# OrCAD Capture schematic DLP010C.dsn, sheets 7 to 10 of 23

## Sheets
7 PAGE 06 - VIRTEX5 - 3: size Custom
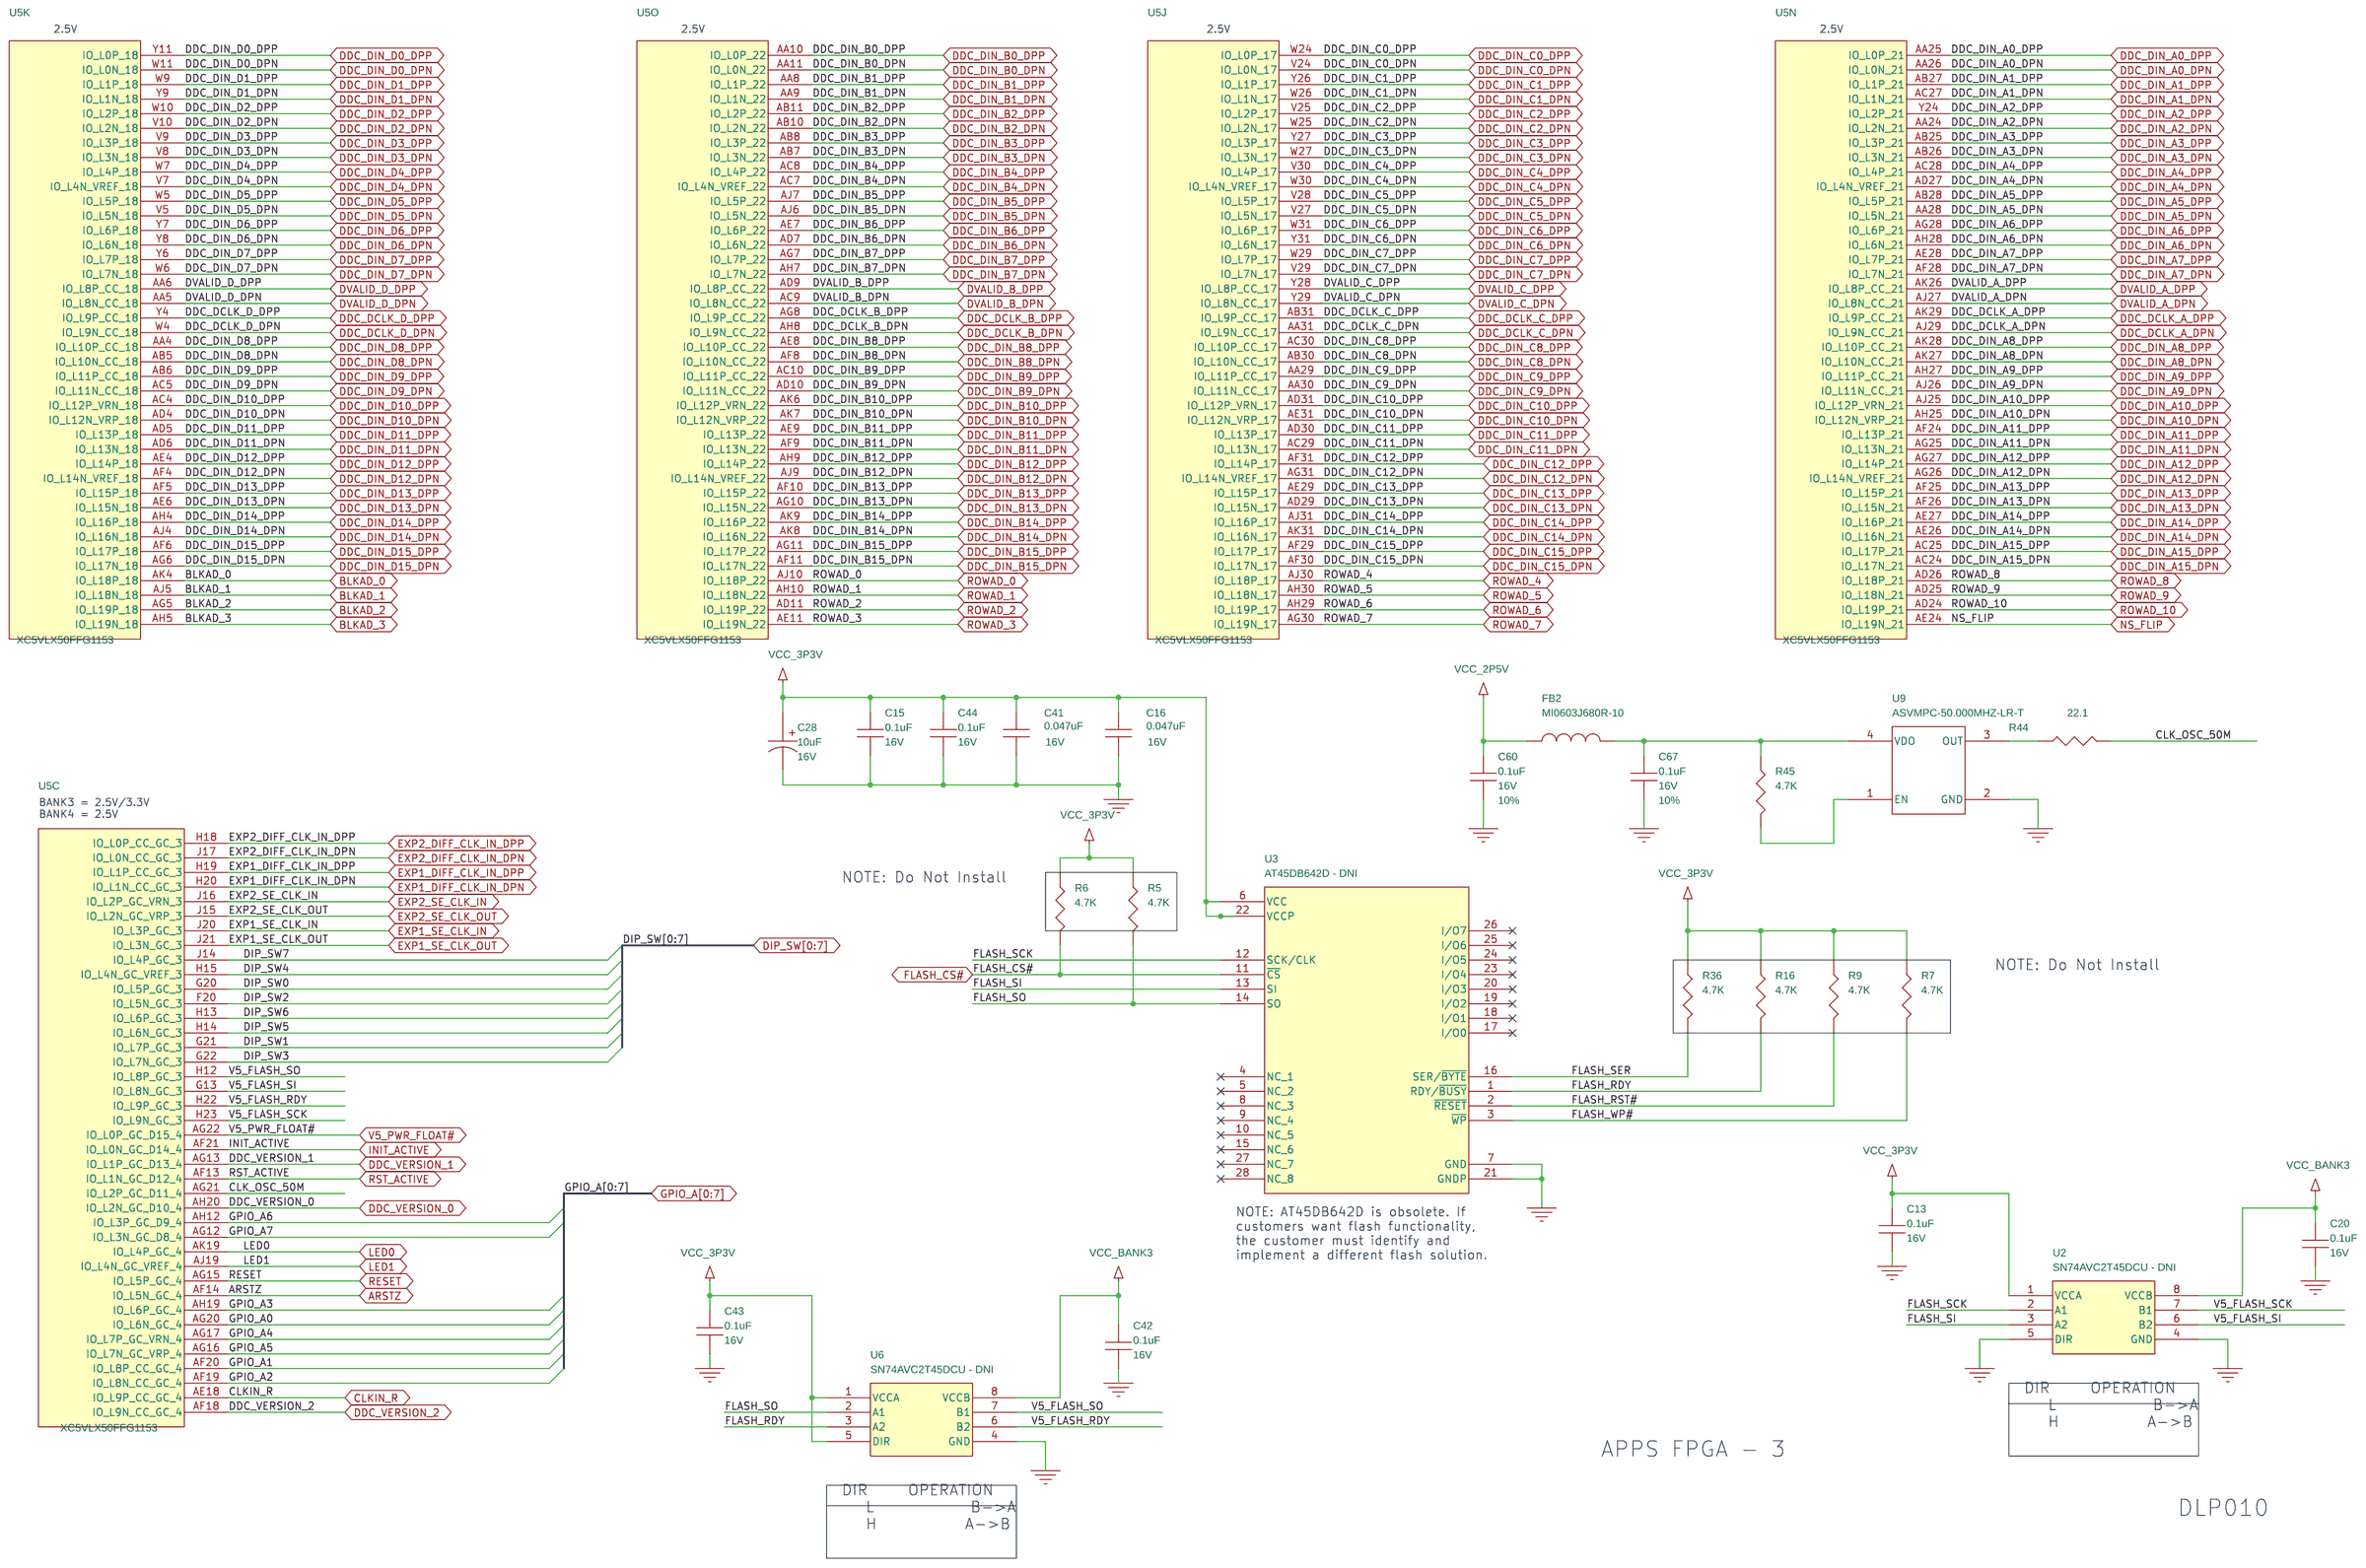
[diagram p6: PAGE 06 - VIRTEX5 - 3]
8 PAGE 07 - VIRTEX5 - 4: size Custom
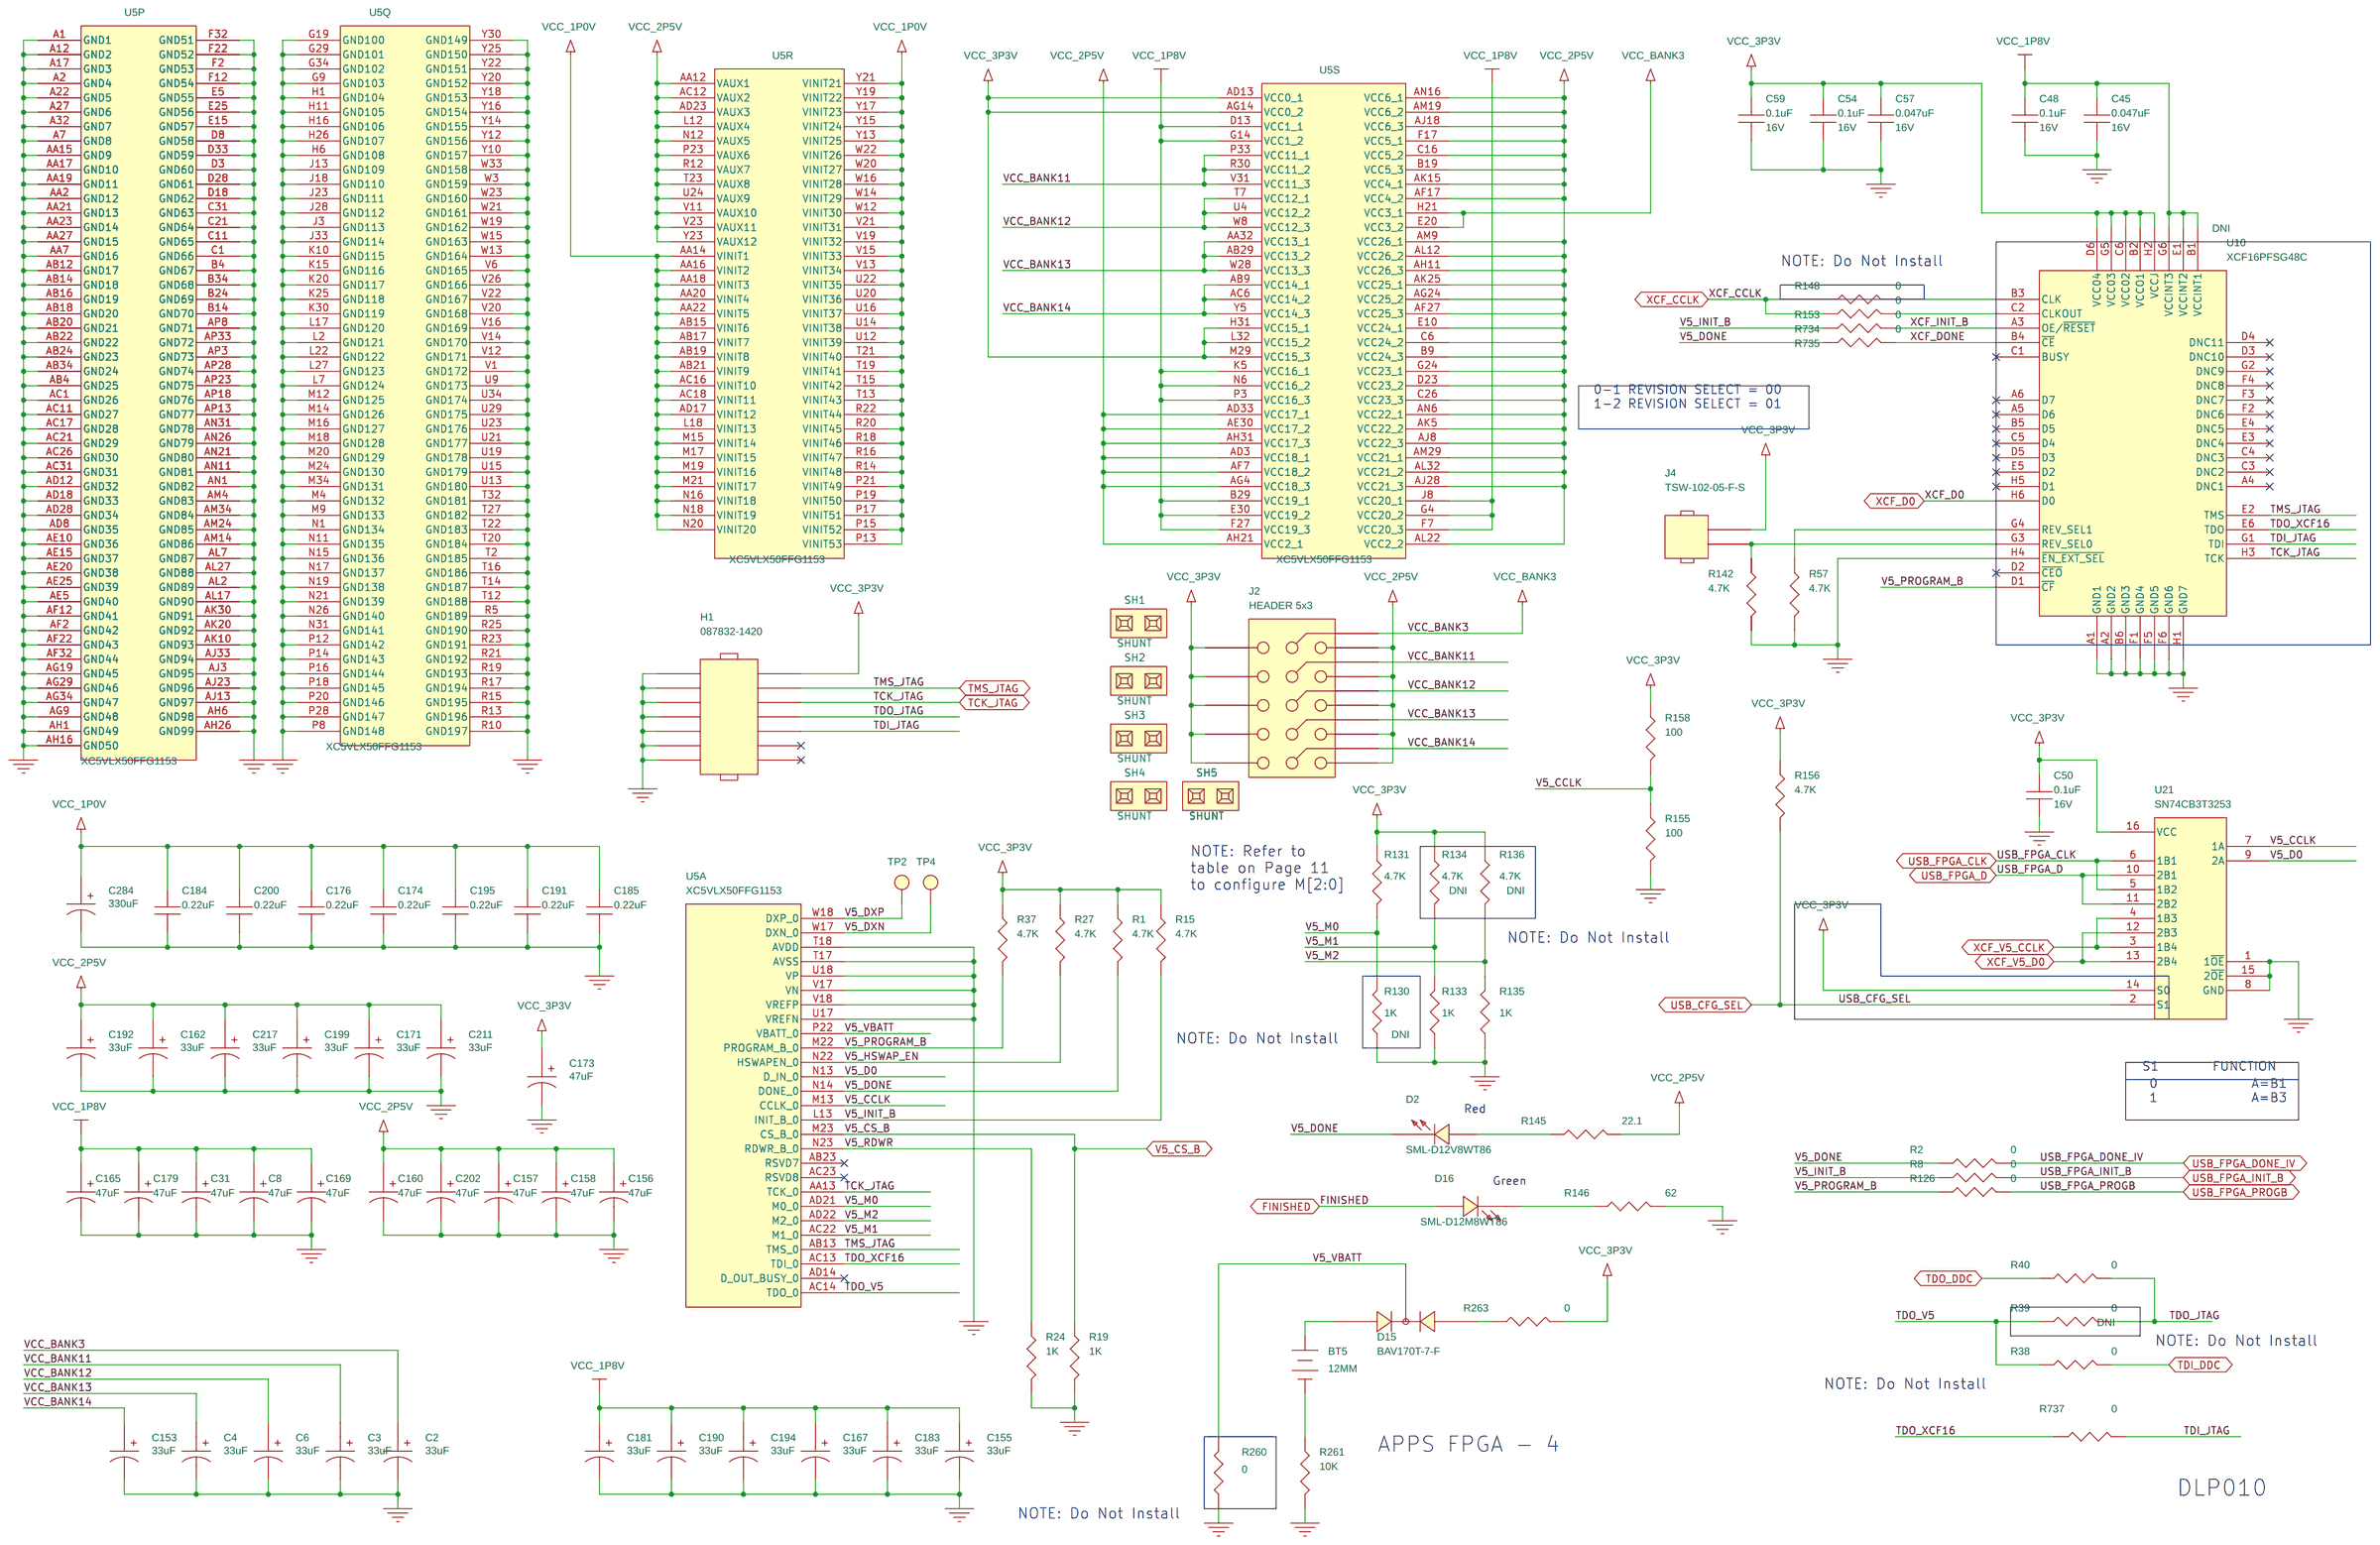
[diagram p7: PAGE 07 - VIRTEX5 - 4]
9 PAGE 08 - DDR2 SO-DIMM: size Custom
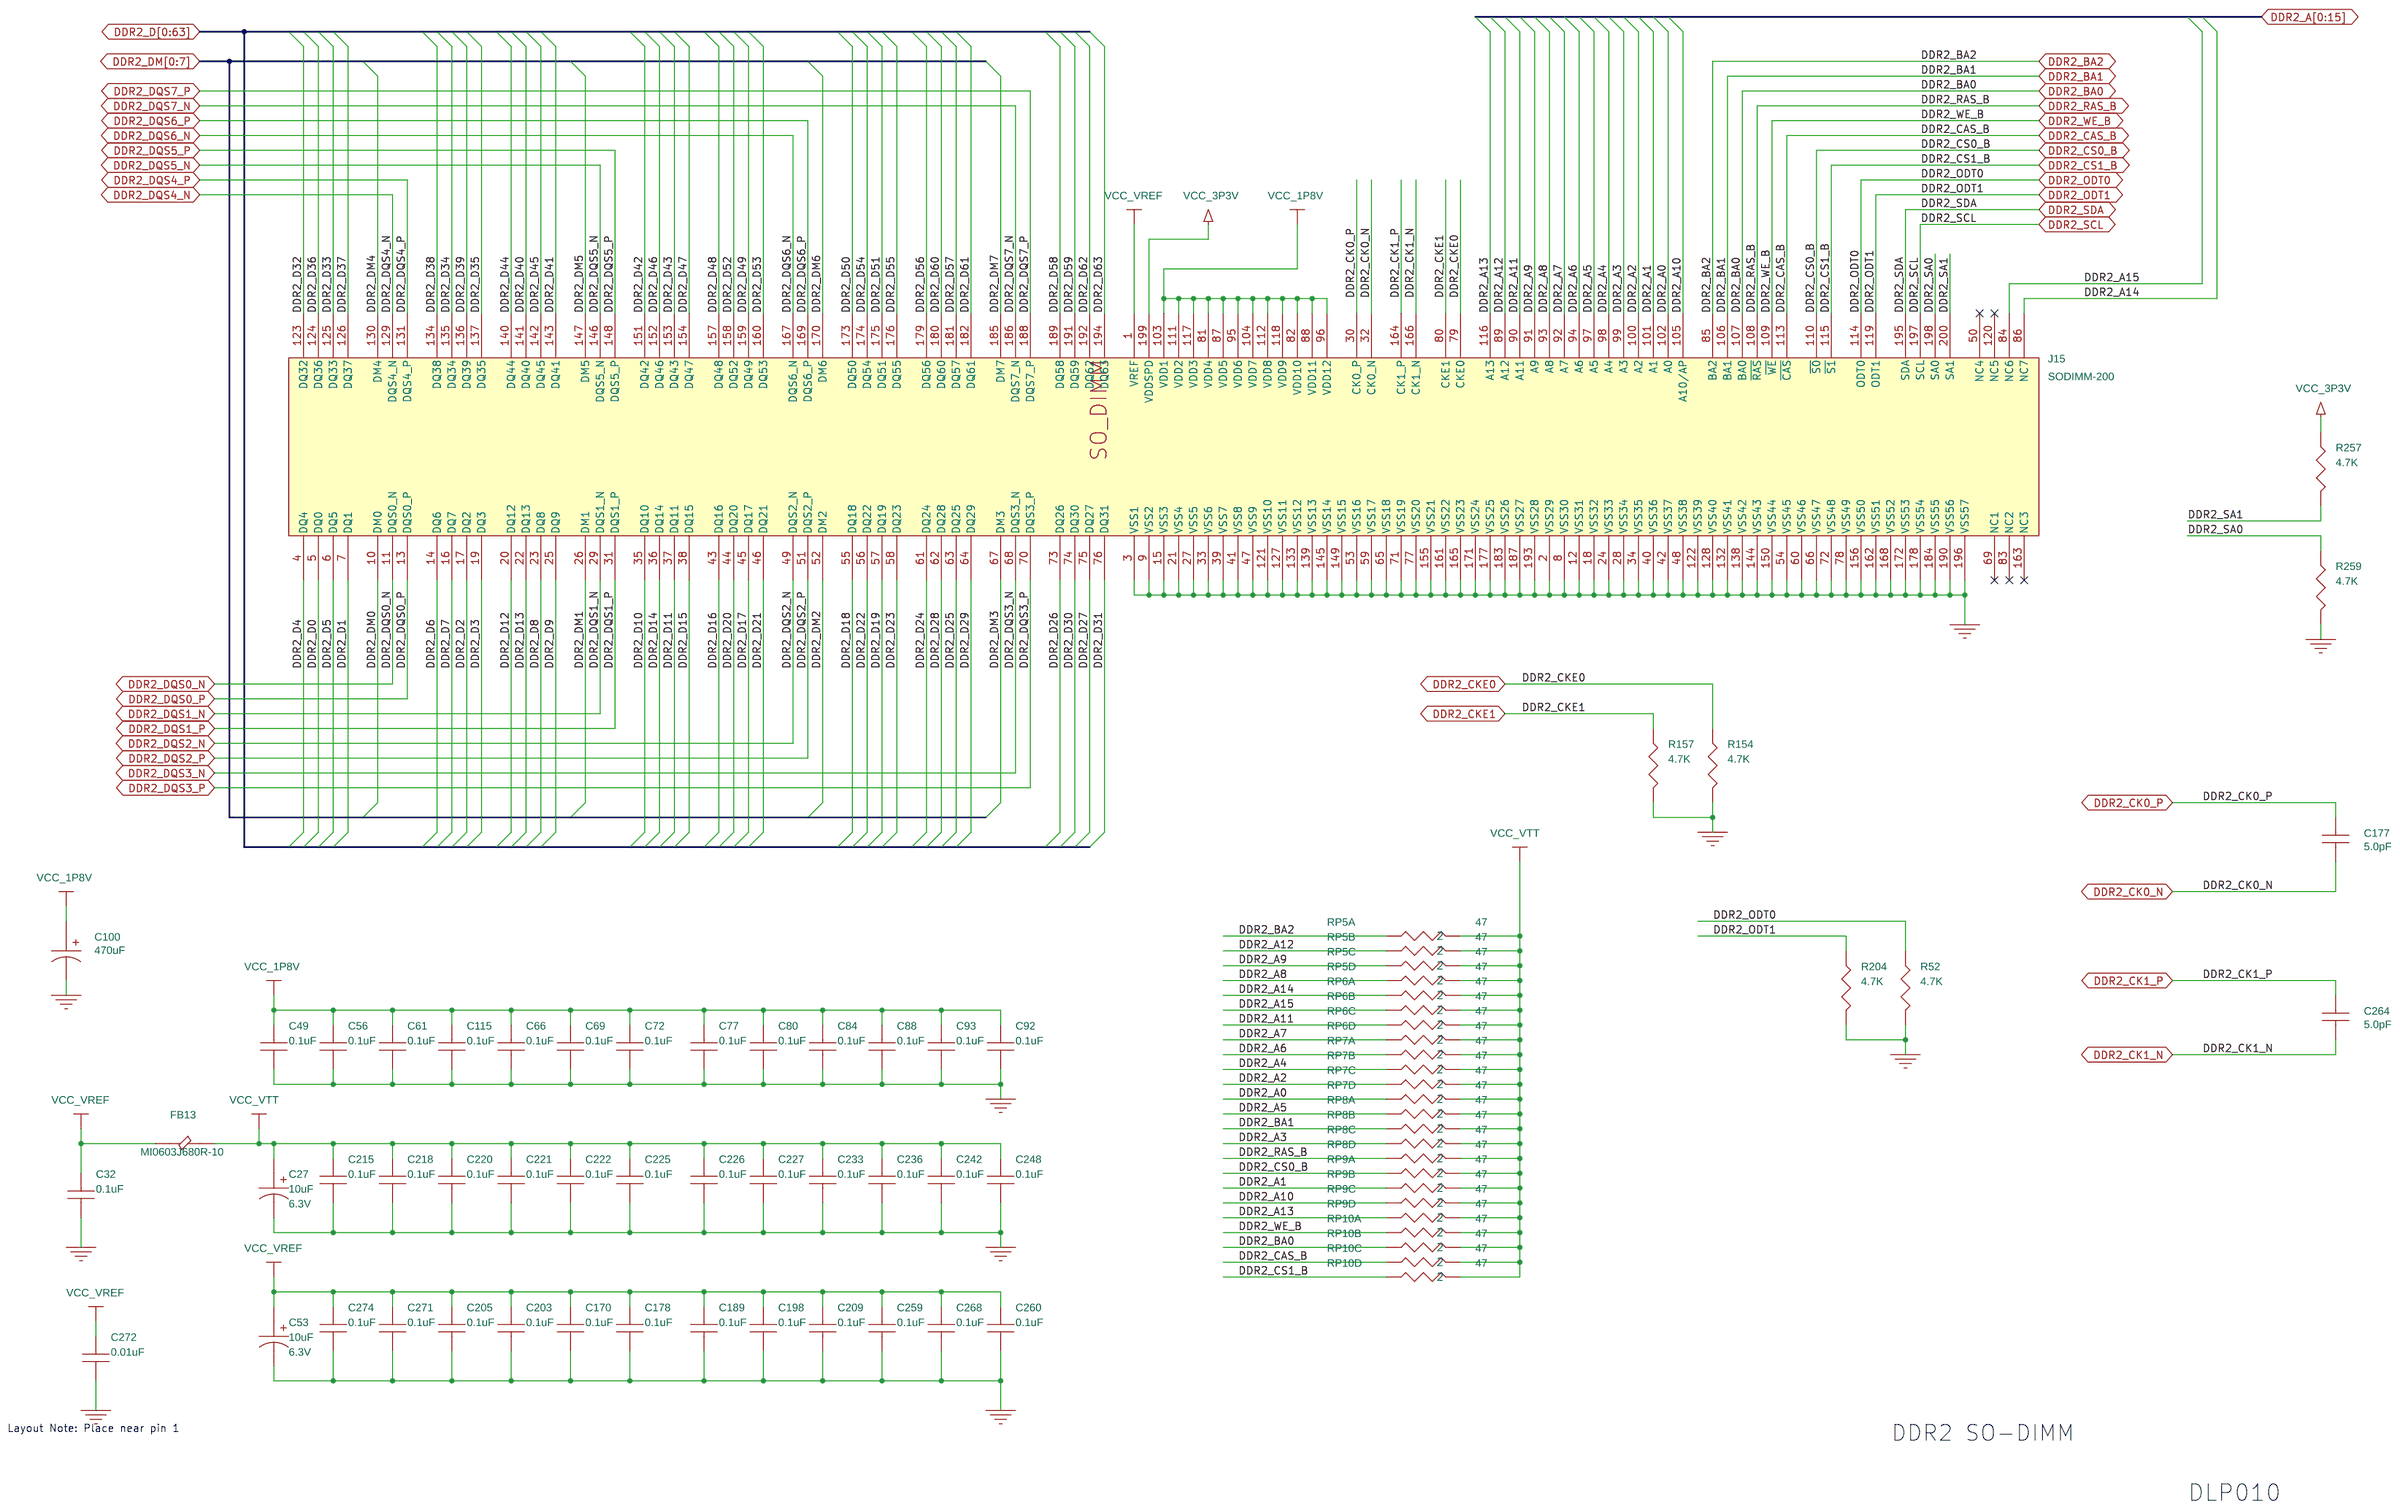
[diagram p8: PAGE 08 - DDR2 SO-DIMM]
10 PAGE 09 - DLPC410 - 1: size Custom
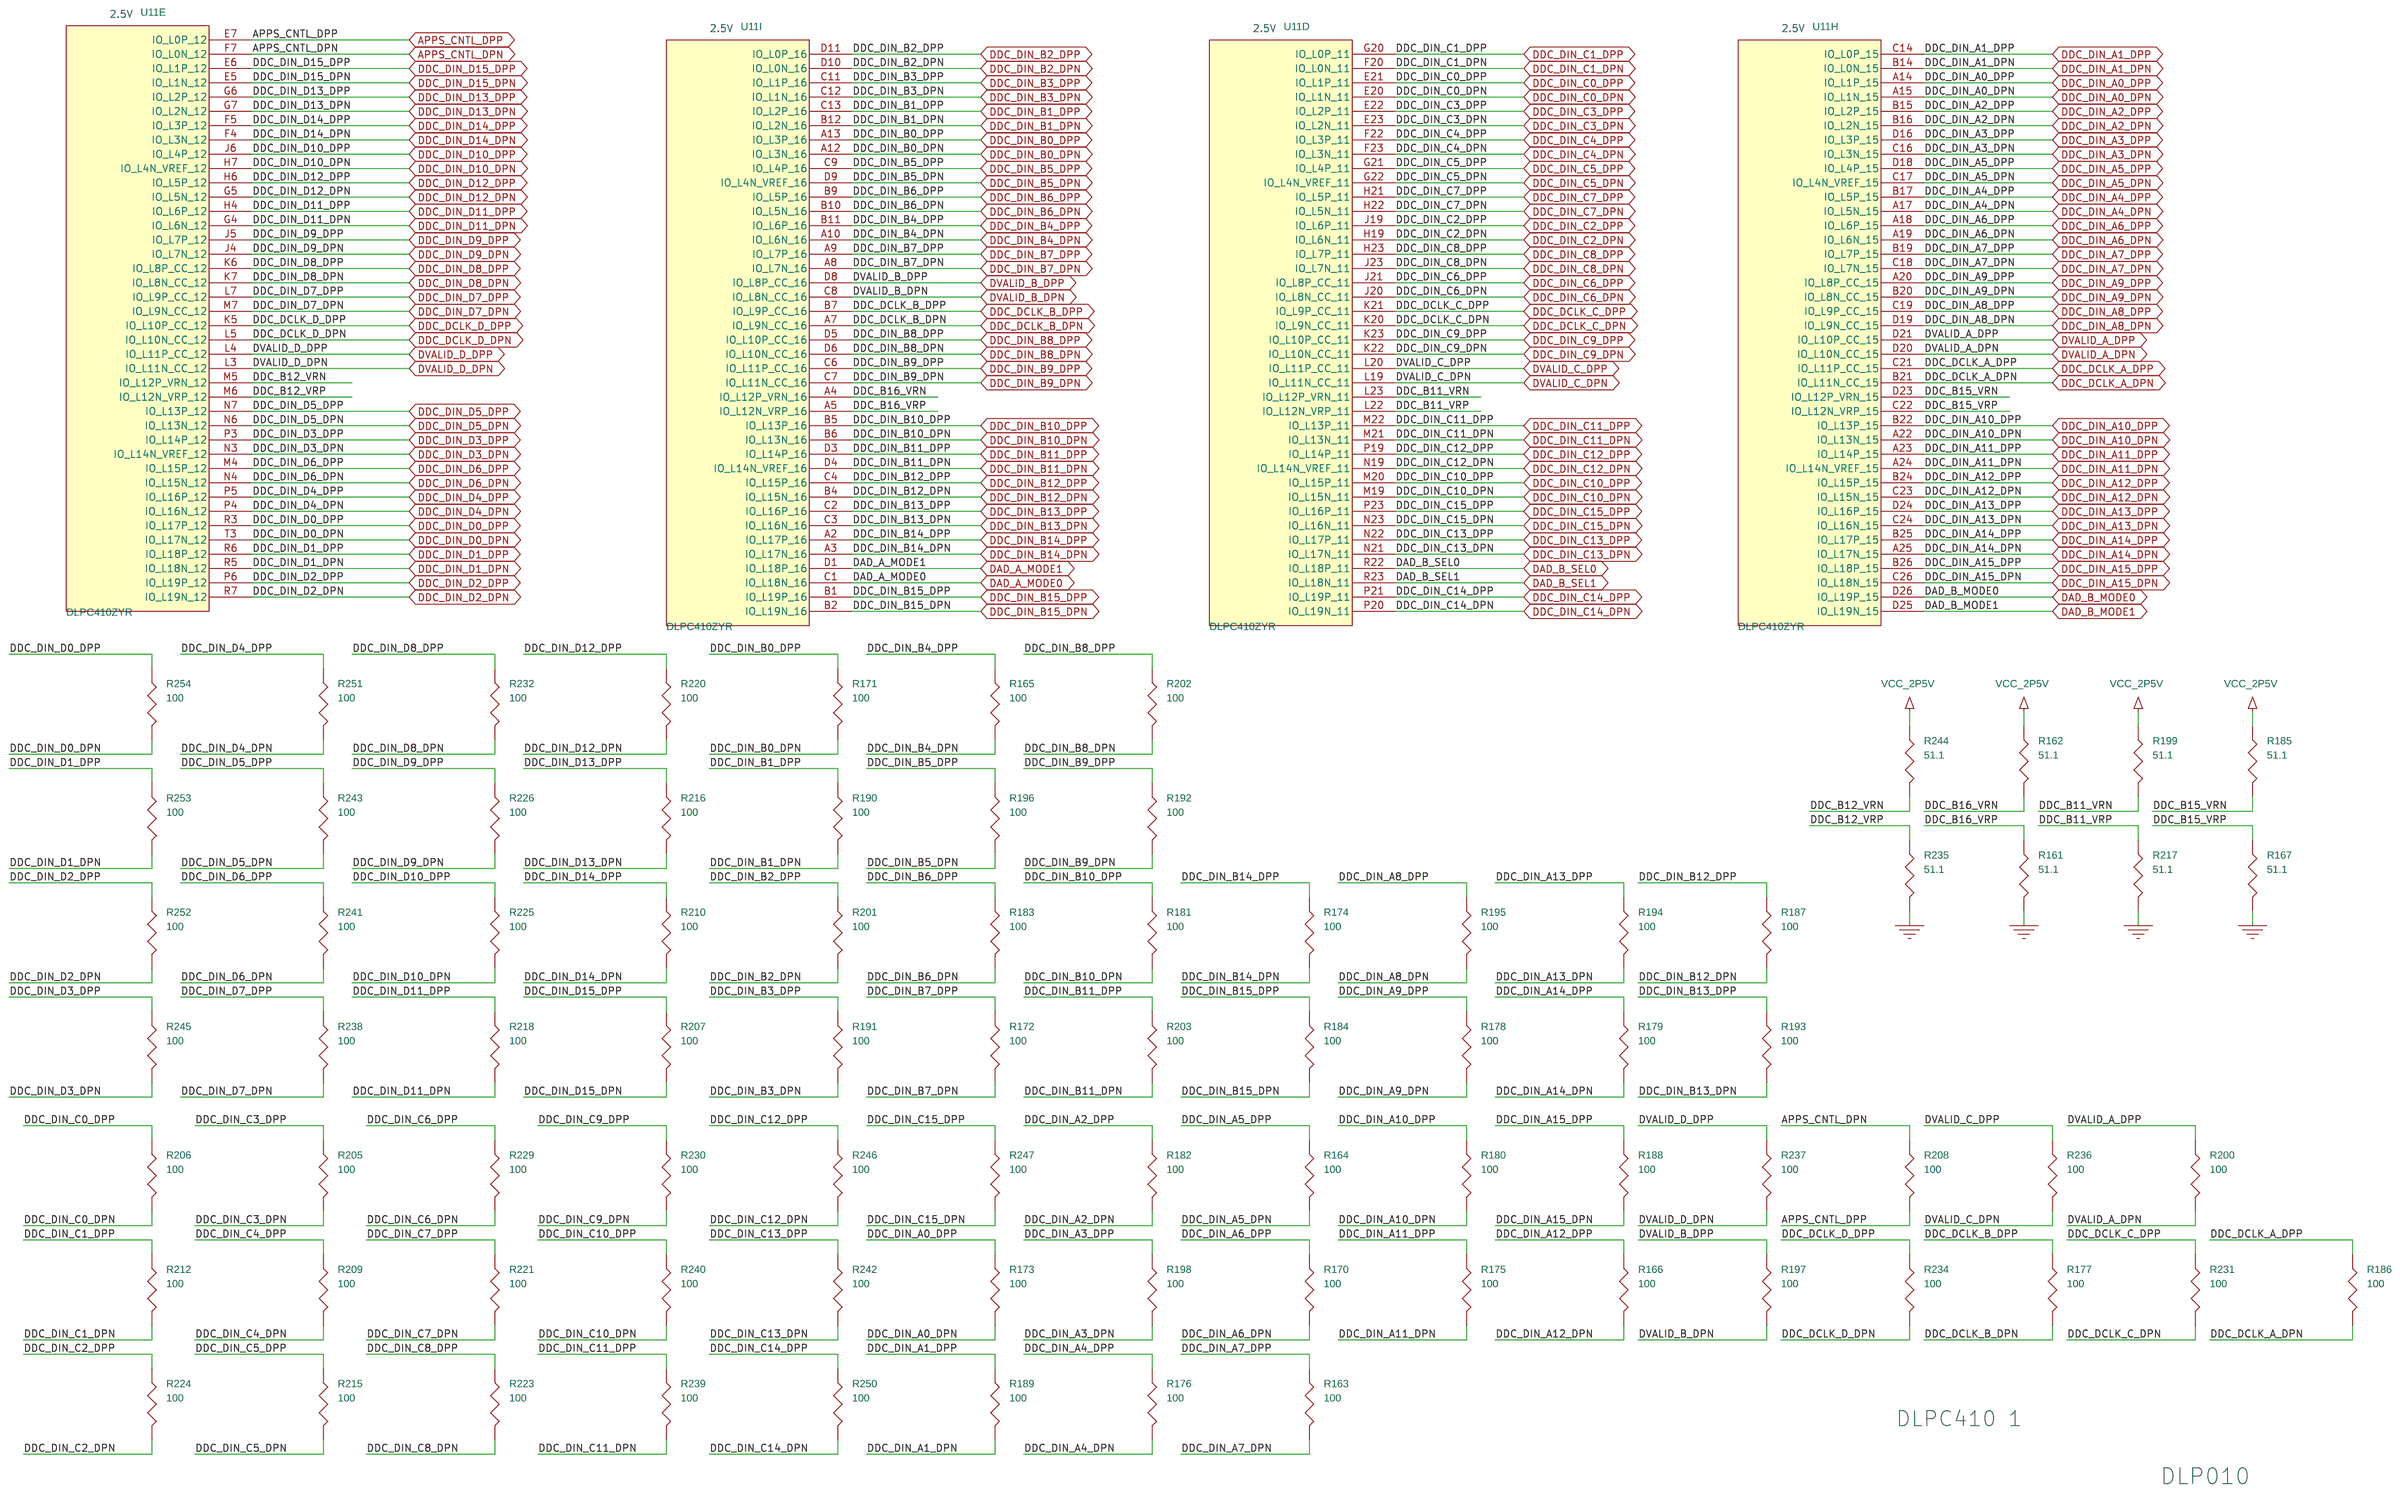
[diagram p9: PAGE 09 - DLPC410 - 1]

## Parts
sheet PAGE 06 - VIRTEX5 - 3
C13  0.1uF  [0603]
C15  0.1uF  [0603]
C16  0.047uF  [0402]
C20  0.1uF  [0603]
C28  10uF  [tant_a]
C41  0.047uF  [0402]
C42  0.1uF  [0603]
C43  0.1uF  [0603]
C44  0.1uF  [0603]
C60  0.1uF  [0603]
C67  0.1uF  [0603]
FB2  MI0603J680R-10  [0603]
R5  4.7K  [0603]
R6  4.7K  [0603]
R7  4.7K  [0603]
R9  4.7K  [0603]
R16  4.7K  [0603]
R36  4.7K  [0603]
R44  22.1  [0603]
R45  4.7K  [0603]
U2  SN74AVC2T45DCU - DNI  [sm_sn74_sop8]
U3  AT45DB642D - DNI  [sm_tsop28_468]
U6  SN74AVC2T45DCU - DNI  [sm_sn74_sop8]
U9  ASVMPC-50.000MHZ-LR-T  [OSC4PIN]
sheet PAGE 07 - VIRTEX5 - 4
BT5  12MM  [12MM]
C2  33uF  [tant_b]
C3  33uF  [tant_b]
C4  33uF  [tant_b]
C6  33uF  [tant_b]
C8  47uF  [tant_b]
C31  47uF  [tant_b]
C45  0.047uF  [0402]
C48  0.1uF  [0603]
C50  0.1uF  [0603]
C54  0.1uF  [0603]
C57  0.047uF  [0402]
C59  0.1uF  [0603]
C153  33uF  [tant_b]
C155  33uF  [tant_b]
C156  47uF  [tant_b]
C157  47uF  [tant_b]
C158  47uF  [tant_b]
C160  47uF  [tant_b]
C162  33uF  [tant_b]
C165  47uF  [tant_b]
C167  33uF  [tant_b]
C169  47uF  [tant_b]
C171  33uF  [tant_b]
C173  47uF  [tant_b]
C174  0.22uF  [0402]
C176  0.22uF  [0402]
C179  47uF  [tant_b]
C181  33uF  [tant_b]
C183  33uF  [tant_b]
C184  0.22uF  [0402]
C185  0.22uF  [0402]
C190  33uF  [tant_b]
C191  0.22uF  [0402]
C192  33uF  [tant_b]
C194  33uF  [tant_b]
C195  0.22uF  [0402]
C199  33uF  [tant_b]
C200  0.22uF  [0402]
C202  47uF  [tant_b]
C211  33uF  [tant_b]
C217  33uF  [tant_b]
C284  330uF  [tant_d]
D2  SML-D12V8WT86  [sm_led_0603]
D15  BAV170T-7-F  [sm_sot523_3]
D16  SML-D12M8WT86  [sm_led_0603]
H1  087832-1420  [hdr7x2]
J2  HEADER 5x3  [TH_HEADER_5x3]
J4  TSW-102-05-F-S  [jumper2]
R1  4.7K  [0603]
R2  0  [0603]
R8  0  [0603]
R15  4.7K  [0603]
R19  1K  [0603]
R24  1K  [0603]
R27  4.7K  [0603]
R37  4.7K  [0603]
R38  0  [0603]
R39  0  [0603]
R40  0  [0603]
R57  4.7K  [0603]
R126  0  [0603]
R130  1K  [0603]
R131  4.7K  [0603]
R133  1K  [0603]
R134  4.7K  [0603]
R135  1K  [0603]
R136  4.7K  [0603]
R142  4.7K  [0603]
R145  22.1  [0603]
R146  62  [0603]
R148  0  [0603]
R153  0  [0603]
R155  100  [0402]
R156  4.7K  [0603]
R158  100  [0402]
R260  0  [0603]
R261  10K  [0603]
R263  0  [0603]
R734  0  [0603]
R735  0  [0603]
R737  0  [0603]
SH1  SHUNT
SH2  SHUNT
SH3  SHUNT
SH4  SHUNT
SH5  SHUNT
TP2  T POINT R  [25MILSQPOST]
TP4  T POINT R  [25MILSQPOST]
U5  XC5VLX50FFG1153  [sm_ff1153]  (sections A,B,C,D,E,F,G,H,I,J,K,L,M,N,O,P,Q,R,S,T,U)
U10  XCF16PFSG48C  [48TFBGA]
U21  SN74CB3T3253  [tssop16]
sheet PAGE 08 - DDR2 SO-DIMM
C27  10uF  [tant_a]
C32  0.1uF  [0603]
C49  0.1uF  [0603]
C53  10uF  [tant_a]
C56  0.1uF  [0603]
C61  0.1uF  [0603]
C66  0.1uF  [0603]
C69  0.1uF  [0603]
C72  0.1uF  [0603]
C77  0.1uF  [0603]
C80  0.1uF  [0603]
C84  0.1uF  [0603]
C88  0.1uF  [0603]
C92  0.1uF  [0603]
C93  0.1uF  [0603]
C100  470uF  [tant_d]
C115  0.1uF  [0603]
C170  0.1uF  [0603]
C177  5.0pF  [0603]
C178  0.1uF  [0603]
C189  0.1uF  [0603]
C198  0.1uF  [0603]
C203  0.1uF  [0603]
C205  0.1uF  [0603]
C209  0.1uF  [0603]
C215  0.1uF  [0603]
C218  0.1uF  [0603]
C220  0.1uF  [0603]
C221  0.1uF  [0603]
C222  0.1uF  [0603]
C225  0.1uF  [0603]
C226  0.1uF  [0603]
C227  0.1uF  [0603]
C233  0.1uF  [0603]
C236  0.1uF  [0603]
C242  0.1uF  [0603]
C248  0.1uF  [0603]
C259  0.1uF  [0603]
C260  0.1uF  [0603]
C264  5.0pF  [0603]
C268  0.1uF  [0603]
C271  0.1uF  [0603]
C272  0.01uF  [0603]
C274  0.1uF  [0603]
FB13  MI0603J680R-10  [0603]
J15  SODIMM-200  [sm_sodimm_59354]
R52  4.7K  [0603]
R154  4.7K  [0603]
R157  4.7K  [0603]
R204  4.7K  [0603]
R257  4.7K  [0603]
R259  4.7K  [0603]
RP5  47  [sm_rp4x0603]  (sections A,B,C,D)
RP6  47  [sm_rp4x0603]  (sections A,B,C,D)
RP7  47  [sm_rp4x0603]  (sections A,B,C,D)
RP8  47  [sm_rp4x0603]  (sections A,B,C,D)
RP9  47  [sm_rp4x0603]  (sections A,B,C,D)
RP10  47  [sm_rp4x0603]  (sections A,B,C,D)
sheet PAGE 09 - DLPC410 - 1
R161  51.1  [0603]
R162  51.1  [0603]
R163  100  [0402]
R164  100  [0402]
R165  100  [0402]
R166  100  [0402]
R167  51.1  [0603]
R170  100  [0402]
R171  100  [0402]
R172  100  [0402]
R173  100  [0402]
R174  100  [0402]
R175  100  [0402]
R176  100  [0402]
R177  100  [0402]
R178  100  [0402]
R179  100  [0402]
R180  100  [0402]
R181  100  [0402]
R182  100  [0402]
R183  100  [0402]
R184  100  [0402]
R185  51.1  [0603]
R186  100  [0402]
R187  100  [0402]
R188  100  [0402]
R189  100  [0402]
R190  100  [0402]
R191  100  [0402]
R192  100  [0402]
R193  100  [0402]
R194  100  [0402]
R195  100  [0402]
R196  100  [0402]
R197  100  [0402]
R198  100  [0402]
R199  51.1  [0603]
R200  100  [0402]
R201  100  [0402]
R202  100  [0402]
R203  100  [0402]
R205  100  [0402]
R206  100  [0402]
R207  100  [0402]
R208  100  [0402]
R209  100  [0402]
R210  100  [0402]
R212  100  [0402]
R215  100  [0402]
R216  100  [0402]
R217  51.1  [0603]
R218  100  [0402]
R220  100  [0402]
R221  100  [0402]
R223  100  [0402]
R224  100  [0402]
R225  100  [0402]
R226  100  [0402]
R229  100  [0402]
R230  100  [0402]
R231  100  [0402]
R232  100  [0402]
R234  100  [0402]
R235  51.1  [0603]
R236  100  [0402]
R237  100  [0402]
R238  100  [0402]
R239  100  [0402]
R240  100  [0402]
R241  100  [0402]
R242  100  [0402]
R243  100  [0402]
R244  51.1  [0603]
R245  100  [0402]
R246  100  [0402]
R247  100  [0402]
R250  100  [0402]
R251  100  [0402]
R252  100  [0402]
R253  100  [0402]
R254  100  [0402]
sheet PAGE 10 - DLPC410 - 2
U11  DLPC410ZYR  [sm_ff676]  (sections A,B,C,D,E,F,G,H,I,J,K,L,M,N,O)

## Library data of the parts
C13 C15 C20 C42-C44 C48 C50 C54 C59 C60 C67 = CAP_NP: Manuf: Kemet; PartNumber: C0603C104K4RACTU; ROOM: V5; Tolerance: 10%; Voltage: 16V
C16 C41 C45 C57 = CAP_NP: Manuf: TDK; PartNumber: C1005X7R1C473K; ROOM: V5; Tolerance: 10%; Voltage: 16V
C28 = CAP_POL: Manuf: AVX; PartNumber: TAJA106K016RNJ; ROOM: V5; Tolerance: 10%; Voltage: 16V
FB2 = INDUCTOR: Current: 1A; Impedance: 68; Manuf: Steward; ROOM: V5
R5-R7 R9 R16 R36 R134 R136 = R_v2: DNI: DNI; Manuf: Panasonic; Notes: DNI; PartNumber: ERJ-3GEYJ472V; ROOM: V5; Tolerance: %1
R44 R145 = R_v2: Manuf: Panasonic; PartNumber: ERJ-3EKF22R1V; ROOM: V5; Tolerance: %1
R1 R15 R27 R37 R45 R57 R131 R142 R156 = R_v2: Manuf: Panasonic; PartNumber: ERJ-3GEYJ472V; ROOM: V5; Tolerance: %1
U2 U6 = SN74AVC2T45DCU: DNI: DNI; Manuf: Texas Instruments; Notes: DNI; PartNumber: SN74AVC2T45DCUR; ROOM: V5
U3 = AT45DB642D: DNI: DNI; Manuf: Atmel; Notes: DNI - Obsolete; PartNumber: AT45DB642D-TU; ROOM: V5
U9 = EC2700TTS-50_0.000M: Freq: 50.000Mhz; Manuf: Abracon; ROOM: V5; Supply Voltage: 2.5V; Tolerance: +/- 100ppm
BT5 = BATTERY: Manuf: KEYSTONE; PartNumber: 500; ROOM: V5
C2-C4 C6 C153 C155 C162 C167 C171 C181 C183 C190 C192 C194 C199 C211 C217 = CAP_POL: Manuf: Kemet; PartNumber: T520B336M006ATE040; ROOM: V5; Tolerance: 20%; Voltage: 6.3V
C8 C31 C156-C158 C160 C165 C169 C173 C179 C202 = CAP_POL: Manuf: Kemet; PartNumber: T520B476M006ATE070; ROOM: V5
C174 C176 C184 C185 C191 C195 C200 = CAP_NP: Manuf: Kemet; PartNumber: C0402C224K9PACTU; ROOM: V5; TempCoeff: X5R; Voltage: 6.3V
C284 = CAP_POL: Manuf: Kemet; PartNumber: T520V337M2R5ATE025; ROOM: V5; Tolerance: 20%; Voltage: 2.5V
D2 D16 = LED: Manuf: ROHM; ROOM: USB
D15 = DIODE_DUAL_CK_AAJ: Manuf: DIODES INC; ROOM: V5
H1 = HEADER_7x2_SM: Manuf: Molex; PartNumber: 0878321420; ROOM: V5
J2 = HEADER_5x3: Manuf: Samtec; PartNumber: TSW-105-07-F-T
J4 = HEADER_2: Manuf: Samtec; PartNumber: TSW-102-07-F-S; ROOM: V5
R2 R8 R126 R153 R263 R734 R735 = R_v2: Manuf: Panasonic; PartNumber: ERJ-3GEY0R00V; ROOM: V5; Tolerance: %1
R19 R24 R133 R135 = R_v2: Manuf: Panasonic; PartNumber: ERJ-3GEYJ102V; ROOM: V5; Tolerance: %1
R38 R40 R737 = R_v2: Manuf: Panasonic; PartNumber: ERJ-3GEY0R00V; ROOM: ROOM_VIRTEX; Tolerance: %1
R39 = R_v2: DNI: DNI; Manuf: Panasonic; Notes: DNI; PartNumber: ERJ-3GEY0R00V; ROOM: ROOM_VIRTEX; Tolerance: %1
R130 = R_v2: DNI: DNI; Manuf: Panasonic; Notes: DNI; PartNumber: ERJ-3GEYJ102V; ROOM: V5
R146 = R_v2: Manuf: Panasonic; PartNumber: ERJ-3GEYJ620V; ROOM: V5; Tolerance: %5
R148 R260 = R_v2: DNI: DNI; Manuf: Panasonic; Notes: DNI; PartNumber: ERJ-3GEY0R00V; ROOM: V5; Tolerance: %1
R155 R158 = R_v2: Manuf: Panasonic; PartNumber: ERJ-2RKF1000X; ROOM: V5
R261 = R_v2: Manuf: Panasonic; PartNumber: ERJ-3GEYJ103V; ROOM: V5; Tolerance: %1
SH1-SH5 = CON2_1: CONN SHUNT SPRING 2POS .100 GOLD; Manuf: AMP; PartNumber: 530153-2
TP2 TP4 = T_POINT_R: DNI: DNI; Manuf: Not-a-part; PartNumber: Not-a-part; ROOM: V5
U5 = XC5VLX50FF1153_13: Manuf: xilinx; PartNumber: XC5VLX50-1FFG1153C; ROOM: V5
U10 = DFM-XCF08P-FSG48C_4: DNI: DNI; Manuf: Xilinx; ROOM: V5
U21 = SN74CB3T3253: Manuf: Texas Instruments; PartNumber: SN74CB3T3253PWR; ROOM: V5
C27 C53 = CAP_POL: Manuf: AVX; PartNumber: TAJA106K006RNJ; ROOM: SODIMM; Tolerance: 10%; Voltage: 6.3V
C32 C49 C56 C61 C66 C69 C72 C77 C80 C84 C88 C92 C93 C115 C170 C178 C189 C198 C203 C205 C209 C215 C218 C220-C222 C225-C227 C233 C236 C242 C248 C259 C260 C268 C271 C274 = CAP_NP: Manuf: Kemet; PartNumber: C0603C104K4RACTU; ROOM: SODIMM; Tolerance: 10%; Voltage: 16V
C100 = CAP_POL: Manuf: AVX; PartNumber: TAJD477K006RNJ; ROOM: SODIMM; TYPE: TANT; VOLTAGE: 6.3V
C177 C264 = CAP_NP: Manuf: AVX; PartNumber: 06031A5R0CAT2A; ROOM: SODIMM; TemperatureCoefficient: C0G; Tolerance: .25pF; Voltage: 100V
C272 = CAP_NP: Manuf: Kemet; PartNumber: C0603C103K5RACTU; ROOM: SODIMM; Tolerance: 10%; Voltage: 50V
FB13 = DFM-BEAD: Manuf: Laird; ROOM: SODIMM; Vendor: STEWARD
J15 = SODIMM-200: Manuf: FCI; PartNumber: 10033853-052FSLF; ROOM: SODIMM
R52 R154 R157 R204 R257 R259 = R_v2: Manuf: Panasonic; PartNumber: ERJ-3GEYJ472V; ROOM: SODIMM; Tolerance: %1
RP5-RP10 = RESISTOR_DIP_4_A-D: Manuf: Panasonic; PartNumber: EXB-V8V470JV; ROOM: SODIMM
R161 R162 R167 R185 R199 R217 R235 R244 = R_v2: Manuf: Panasonic; PartNumber: ERJ-3EKF51R1V; ROOM: DDC4100; Tolerance: %1
R163-R166 R170-R184 R186-R198 R200-R203 R205-R210 R212 R215 R216 R218 R220 R221 R223-R226 R229-R232 R234 R236-R243 R245-R247 R250-R254 = R_v2: Manuf: Panasonic; PartNumber: ERJ-2RKF1000X; ROOM: DDC4100_termination
U11 = XC5VLX30FF676: Manuf: Texas Instruments; ROOM: DDC4100

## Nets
GND: C2.2 C3.2 C4.2 C6.2 C8.2 C13.2 C15.2 C16.2 C20.2 C27.2 C28.2 C31.2 C32.2 C41.2 C42.2 C43.2 C44.2 C45.2 C48.2 C49.2 C50.2 C53.2 C54.2 C56.2 C57.2 C59.2 C60.2 C61.2 C66.2 C67.2 C69.2 C72.2 C77.2 C80.2 C84.2 C88.2 C92.2 C93.2 C100.2 C115.2 C153.2 C155.2 C156.2 C157.2 C158.2 C160.2 C162.2 C165.2 C167.2 C169.2 C170.2 C171.2 C173.2 C174.2 C176.2 C178.2 C179.2 C181.2 C183.2 C184.2 C185.2 C189.2 C190.2 C191.2 C192.2 C194.2 C195.2 C198.2 C199.2 C200.2 C202.2 C203.2 C205.2 C209.2 C211.2 C215.2 C217.2 C218.2 C220.2 C221.2 C222.2 C225.2 C226.2 C227.2 C233.2 C236.2 C242.2 C248.2 C259.2 C260.2 C268.2 C271.2 C272.2 C274.2 C284.2 H1.1 H1.3 H1.5 H1.7 H1.9 H1.11 H1.13 J15.2(VSS29) J15.3(VSS1) J15.8(VSS30) J15.9(VSS2) J15.12(VSS31) J15.15(VSS3) J15.18(VSS32) J15.21(VSS4) J15.24(VSS33) J15.27(VSS5) J15.28(VSS34) J15.33(VSS6) J15.34(VSS35) J15.39(VSS7) J15.40(VSS36) J15.41(VSS8) J15.42(VSS37) J15.47(VSS9) J15.48(VSS38) J15.53(VSS16) J15.54(VSS45) J15.59(VSS17) J15.60(VSS46) J15.65(VSS18) J15.66(VSS47) J15.71(VSS19) J15.72(VSS48) J15.77(VSS20) J15.78(VSS49) J15.121(VSS10) J15.122(VSS39) J15.127(VSS11) J15.128(VSS40) J15.132(VSS41) J15.133(VSS12) J15.138(VSS42) J15.139(VSS13) J15.144(VSS43) J15.145(VSS14) J15.149(VSS15) J15.150(VSS44) J15.155(VSS21) J15.156(VSS50) J15.161(VSS22) J15.162(VSS51) J15.165(VSS23) J15.168(VSS52) J15.171(VSS24) J15.172(VSS53) J15.177(VSS25) J15.178(VSS54) J15.183(VSS26) J15.184(VSS55) J15.187(VSS27) J15.190(VSS56) J15.193(VSS28) J15.196(VSS57) R19.2 R24.2 R52.2 R57.2 R130.1 R133.1 R135.1 R142.2 R146.2 R154.2 R155.2 R157.2 R161.2 R167.2 R204.2 R217.2 R235.2 R259.2 R260.1 R261.2 U2.4(GND) U2.5(DIR) U3.7(GND) U3.21(GNDP) U5.A1(GND1) U5.A2(GND4) U5.A7(GND8) U5.A12(GND2) U5.A17(GND3) U5.A22(GND5) U5.A27(GND6) U5.A32(GND7) U5.AA2(GND12) U5.AA7(GND16) U5.AA15(GND9) U5.AA17(GND10) U5.AA19(GND11) U5.AA21(GND13) U5.AA23(GND14) U5.AA27(GND15) U5.AB4(GND25) U5.AB12(GND17) U5.AB14(GND18) U5.AB16(GND19) U5.AB18(GND20) U5.AB20(GND21) U5.AB22(GND22) U5.AB24(GND23) U5.AB34(GND24) U5.AC1(GND26) U5.AC11(GND27) U5.AC17(GND28) U5.AC21(GND29) U5.AC26(GND30) U5.AC31(GND31) U5.AD8(GND35) U5.AD12(GND32) U5.AD18(GND33) U5.AD28(GND34) U5.AE5(GND40) U5.AE10(GND36) U5.AE15(GND37) U5.AE20(GND38) U5.AE25(GND39) U5.AF2(GND42) U5.AF12(GND41) U5.AF22(GND43) U5.AF32(GND44) U5.AG9(GND48) U5.AG19(GND45) U5.AG29(GND46) U5.AG34(GND47) U5.AH1(GND49) U5.AH6(GND98) U5.AH16(GND50) U5.AH26(GND99) U5.AJ3(GND95) U5.AJ13(GND97) U5.AJ23(GND96) U5.AJ33(GND94) U5.AK10(GND93) U5.AK20(GND92) U5.AK30(GND91) U5.AL2(GND89) U5.AL7(GND87) U5.AL17(GND90) U5.AL27(GND88) U5.AM4(GND83) U5.AM14(GND86) U5.AM24(GND85) U5.AM34(GND84) U5.AN1(GND82) U5.AN11(GND81) U5.AN21(GND80) U5.AN26(GND79) U5.AN31(GND78) U5.AP3(GND73) U5.AP8(GND71) U5.AP13(GND77) U5.AP18(GND76) U5.AP23(GND75) U5.AP28(GND74) U5.AP33(GND72) U5.B4(GND67) U5.B14(GND70) U5.B24(GND69) U5.B34(GND68) U5.C1(GND66) U5.C11(GND65) U5.C21(GND64) U5.C31(GND63) U5.D3(GND60) U5.D8(GND58) U5.D18(GND62) U5.D28(GND61) U5.D33(GND59) U5.E5(GND55) U5.E15(GND57) U5.E25(GND56) U5.F2(GND53) U5.F12(GND54) U5.F22(GND52) U5.F32(GND51) U5.G9(GND103) U5.G19(GND100) U5.G29(GND101) U5.G34(GND102) U5.H1(GND104) U5.H6(GND108) U5.H11(GND105) U5.H16(GND106) U5.H26(GND107) U5.J3(GND113) U5.J13(GND109) U5.J18(GND110) U5.J23(GND111) U5.J28(GND112) U5.J33(GND114) U5.K10(GND115) U5.K15(GND116) U5.K20(GND117) U5.K25(GND118) U5.K30(GND119) U5.L2(GND121) U5.L7(GND124) U5.L17(GND120) U5.L22(GND122) U5.L27(GND123) U5.M4(GND132) U5.M9(GND133) U5.M12(GND125) U5.M14(GND126) U5.M16(GND127) U5.M18(GND128) U5.M20(GND129) U5.M24(GND130) U5.M34(GND131) U5.N1(GND134) U5.N11(GND135) U5.N15(GND136) U5.N17(GND137) U5.N19(GND138) U5.N21(GND139) U5.N26(GND140) U5.N31(GND141) U5.P8(GND148) U5.P12(GND142) U5.P14(GND143) U5.P16(GND144) U5.P18(GND145) U5.P20(GND146) U5.P28(GND147) U5.R5(GND189) U5.R10(GND197) U5.R13(GND196) U5.R15(GND195) U5.R17(GND194) U5.R19(GND193) U5.R21(GND192) U5.R23(GND191) U5.R25(GND190) U5.T2(GND185) U5.T12(GND188) U5.T14(GND187) U5.T16(GND186) U5.T17(AVSS) U5.T18(AVDD) U5.T20(GND184) U5.T22(GND183) U5.T27(GND182) U5.T32(GND181) U5.U9(GND173) U5.U13(GND180) U5.U15(GND179) U5.U17(VREFN) U5.U18(VP) U5.U19(GND178) U5.U21(GND177) U5.U23(GND176) U5.U29(GND175) U5.U34(GND174) U5.V1(GND172) U5.V6(GND165) U5.V12(GND171) U5.V14(GND170) U5.V16(GND169) U5.V17(VN) U5.V18(VREFP) U5.V20(GND168) U5.V22(GND167) U5.V26(GND166) U5.W3(GND159) U5.W13(GND164) U5.W15(GND163) U5.W19(GND162) U5.W21(GND161) U5.W23(GND160) U5.W33(GND158) U5.Y10(GND157) U5.Y12(GND156) U5.Y14(GND155) U5.Y16(GND154) U5.Y18(GND153) U5.Y20(GND152) U5.Y22(GND151) U5.Y25(GND150) U5.Y30(GND149) U6.4(GND) U9.2(GND) U10.A1(GND1) U10.A2(GND2) U10.B6(GND3) U10.F1(GND4) U10.F5(GND5) U10.F6(GND6) U10.H1(GND7) U10.H4(~{EN_EXT_SEL}) U21.1(1~{OE}) U21.8(GND) U21.15(2~{OE}) ; also on sheet 4 6 11 12 13 14 15 16 17 18 19 20 21 22
V5_CCLK: R155.1 R158.2 U5.M13(CCLK_0) U21.7(1A)
V5_CS_B: R19.1 U5.M23(CS_B_0) ; also on sheet 6
V5_D0: U5.N13(D_IN_0) U21.9(2A)
V5_DONE: D2.2(CATHODE) R1.2 R2.1 R735.1 U5.N14(DONE_0)
V5_DXN: TP4.1(TP) U5.W17(DXN_0)
V5_DXP: TP2.1(TP) U5.W18(DXP_0)
V5_FLASH_RDY: U5.H22(IO_L9P_GC_3) U6.6(B2)
V5_FLASH_SCK: U2.7(B1) U5.H23(IO_L9N_GC_3)
V5_FLASH_SI: U2.6(B2) U5.G13(IO_L8N_GC_3)
V5_FLASH_SO: U5.H12(IO_L8P_GC_3) U6.7(B1)
V5_HSWAP_EN: R27.2 U5.N22(HSWAPEN_0)
V5_INIT_B: R8.1 R15.2 R734.1 U5.L13(INIT_B_0)
V5_M0: R130.2 R131.2 U5.AD21(M0_0)
V5_M1: R133.2 R134.2 U5.AC22(M1_0)
V5_M2: R135.2 R136.2 U5.AD22(M2_0)
V5_PROGRAM_B: R37.2 R126.1 U5.M22(PROGRAM_B_0) U10.D1(~{CF})
V5_PWR_FLOAT#: U5.AG22(IO_L0P_GC_D15_4) ; also on sheet 11
V5_RDWR: R24.1 U5.N23(RDWR_B_0)
V5_VBATT: D15.3 R260.2 U5.P22(VBATT_0)
VCC_1P0V: C174.1 C176.1 C184.1 C185.1 C191.1 C195.1 C200.1 C284.1 U5.AA14(VINIT1) U5.AA16(VINIT2) U5.AA18(VINIT3) U5.AA20(VINIT4) U5.AA22(VINIT5) U5.AB15(VINIT6) U5.AB17(VINIT7) U5.AB19(VINIT8) U5.AB21(VINIT9) U5.AC16(VINIT10) U5.AC18(VINIT11) U5.AD17(VINIT12) U5.L18(VINIT13) U5.M15(VINIT14) U5.M17(VINIT15) U5.M19(VINIT16) U5.M21(VINIT17) U5.N16(VINIT18) U5.N18(VINIT19) U5.N20(VINIT20) U5.P13(VINIT53) U5.P15(VINIT52) U5.P17(VINIT51) U5.P19(VINIT50) U5.P21(VINIT49) U5.R14(VINIT48) U5.R16(VINIT47) U5.R18(VINIT46) U5.R20(VINIT45) U5.R22(VINIT44) U5.T13(VINIT43) U5.T15(VINIT42) U5.T19(VINIT41) U5.T21(VINIT40) U5.U12(VINIT39) U5.U14(VINIT38) U5.U16(VINIT37) U5.U20(VINIT36) U5.U22(VINIT35) U5.V13(VINIT34) U5.V15(VINIT33) U5.V19(VINIT32) U5.V21(VINIT31) U5.W12(VINIT30) U5.W14(VINIT29) U5.W16(VINIT28) U5.W20(VINIT27) U5.W22(VINIT26) U5.Y13(VINIT25) U5.Y15(VINIT24) U5.Y17(VINIT23) U5.Y19(VINIT22) U5.Y21(VINIT21) ; also on sheet 20
VCC_1P8V: C8.1 C31.1 C45.1 C48.1 C49.1 C56.1 C61.1 C66.1 C69.1 C72.1 C77.1 C80.1 C84.1 C88.1 C92.1 C93.1 C100.1 C115.1 C155.1 C165.1 C167.1 C169.1 C179.1 C181.1 C183.1 C190.1 C194.1 J15.81(VDD4) J15.82(VDD10) J15.87(VDD5) J15.88(VDD11) J15.95(VDD6) J15.96(VDD12) J15.103(VDD1) J15.104(VDD7) J15.111(VDD2) J15.112(VDD8) J15.117(VDD3) J15.118(VDD9) U5.B29(VCC19_1) U5.D13(VCC1_1) U5.E30(VCC19_2) U5.F7(VCC20_3) U5.F27(VCC19_3) U5.G4(VCC20_2) U5.G14(VCC1_2) U5.J8(VCC20_1) U5.K5(VCC16_1) U5.N6(VCC16_2) U5.P3(VCC16_3) U10.B1(VCCINT1) U10.E1(VCCINT2) U10.G6(VCCINT3) ; also on sheet 4 6 12 19
VCC_2P5V: C60.1 C156.1 C157.1 C158.1 C160.1 C162.1 C171.1 C192.1 C199.1 C202.1 C211.1 C217.1 FB2.1 J2.3 J2.6 J2.9 J2.12 J2.15 R145.2 R162.1 R185.1 R199.1 R244.1 U5.AA12(VAUX1) U5.AC12(VAUX2) U5.AD3(VCC18_1) U5.AD23(VAUX3) U5.AD33(VCC17_1) U5.AE30(VCC17_2) U5.AF7(VCC18_2) U5.AF17(VCC4_2) U5.AF27(VCC25_3) U5.AG4(VCC18_3) U5.AG24(VCC25_2) U5.AH11(VCC26_3) U5.AH21(VCC2_1) U5.AH31(VCC17_3) U5.AJ8(VCC22_3) U5.AJ18(VCC6_3) U5.AJ28(VCC21_3) U5.AK5(VCC22_2) U5.AK15(VCC4_1) U5.AK25(VCC25_1) U5.AL12(VCC26_2) U5.AL22(VCC2_2) U5.AL32(VCC21_2) U5.AM9(VCC26_1) U5.AM19(VCC6_2) U5.AM29(VCC21_1) U5.AN6(VCC22_1) U5.AN16(VCC6_1) U5.B9(VCC24_3) U5.B19(VCC5_3) U5.C6(VCC24_2) U5.C16(VCC5_2) U5.C26(VCC23_3) U5.D23(VCC23_2) U5.E10(VCC24_1) U5.F17(VCC5_1) U5.G24(VCC23_1) U5.L12(VAUX4) U5.N12(VAUX5) U5.P23(VAUX6) U5.R12(VAUX7) U5.T23(VAUX8) U5.U24(VAUX9) U5.V11(VAUX10) U5.V23(VAUX11) U5.Y23(VAUX12) ; also on sheet 4 5 6 11 12 13 14 17 18 19
VCC_3P3V: C13.1 C15.1 C16.1 C28.1 C41.1 C43.1 C44.1 C50.1 C54.1 C57.1 C59.1 C173.1 H1.2 J2.1 J2.4 J2.7 J2.10 J2.13 J4.1 J15.199(VDDSPD) R1.1 R5.1 R6.1 R7.1 R9.1 R15.1 R16.1 R27.1 R36.1 R37.1 R131.1 R134.1 R136.1 R156.1 R158.1 R257.1 R263.2 U2.1(VCCA) U3.6(VCC) U3.22(VCCP) U5.AD13(VCC0_1) U5.AG14(VCC0_2) U5.H31(VCC15_1) U5.L32(VCC15_2) U5.M29(VCC15_3) U6.1(VCCA) U6.5(DIR) U10.B2(VCCO1) U10.C6(VCC02) U10.D6(VCC04) U10.G5(VCC03) U10.H2(VCCJ) U21.14(S0) U21.16(VCC) ; also on sheet 4 5 6 12 15 16 17 18 19 21 22
VCC_BANK3: C2.1 C20.1 C42.1 J2.2 U2.8(VCCB) U5.E20(VCC3_2) U5.H21(VCC3_1) U6.8(VCCB) ; also on sheet 4
VCC_BANK11: C3.1 J2.5 U5.P33(VCC11_1) U5.R30(VCC11_2) U5.V31(VCC11_3)
VCC_BANK12: C6.1 J2.8 U5.T7(VCC12_1) U5.U4(VCC12_2) U5.W8(VCC12_3)
VCC_BANK13: C4.1 J2.11 U5.AA32(VCC13_1) U5.AB29(VCC13_2) U5.W28(VCC13_3)
VCC_BANK14: C153.1 J2.14 U5.AB9(VCC14_1) U5.AC6(VCC14_2) U5.Y5(VCC14_3)
VCC_VREF: C32.1 C53.1 C170.1 C178.1 C189.1 C198.1 C203.1 C205.1 C209.1 C259.1 C260.1 C268.1 C271.1 C272.1 C274.1 FB13.1 J15.1(VREF) ; also on sheet 6 19
VCC_VTT: C27.1 C215.1 C218.1 C220.1 C221.1 C222.1 C225.1 C226.1 C227.1 C233.1 C236.1 C242.1 C248.1 FB13.2 RP5.5(2) RP5.6(2) RP5.7(2) RP5.8(2) RP6.5(2) RP6.6(2) RP6.7(2) RP6.8(2) RP7.5(2) RP7.6(2) RP7.7(2) RP7.8(2) RP8.5(2) RP8.6(2) RP8.7(2) RP8.8(2) RP9.5(2) RP9.6(2) RP9.7(2) RP9.8(2) RP10.5(2) RP10.6(2) RP10.7(2) RP10.8(2)
APPS_CNTL_DPN: R208.1 U11.F7(IO_L0N_12) ; also on sheet 6
APPS_CNTL_DPP: R208.2 U11.E7(IO_L0P_12) ; also on sheet 6
ARSTZ: U5.AF14(IO_L5N_GC_4) ; also on sheet 11
BLKAD_0: U5.AK4(IO_L18P_18) ; also on sheet 11
BLKAD_1: U5.AJ5(IO_L18N_18) ; also on sheet 11
BLKAD_2: U5.AG5(IO_L19P_18) ; also on sheet 11
BLKAD_3: U5.AH5(IO_L19N_18) ; also on sheet 11
CLK_OSC_50M: R44.2 U5.AG21(IO_L2P_GC_D11_4)
CLKIN_R: U5.AE18(IO_L9P_CC_GC_4) ; also on sheet 11
DAD_A_MODE0: U11.C1(IO_L18N_16) ; also on sheet 13
DAD_A_MODE1: U11.D1(IO_L18P_16) ; also on sheet 13
DAD_B_MODE0: U11.D26(IO_L19P_15) ; also on sheet 14
DAD_B_MODE1: U11.D25(IO_L19N_15) ; also on sheet 14
DAD_B_SEL0: U11.R22(IO_L18P_11) ; also on sheet 14
DAD_B_SEL1: U11.R23(IO_L18N_11) ; also on sheet 14
DDC_B11_VRN: R199.2 U11.L23(IO_L12P_VRN_11)
DDC_B11_VRP: R217.1 U11.L22(IO_L12N_VRP_11)
DDC_B12_VRN: R244.2 U11.M5(IO_L12P_VRN_12)
DDC_B12_VRP: R235.1 U11.M6(IO_L12N_VRP_12)
DDC_B15_VRN: R185.2 U11.D23(IO_L12P_VRN_15)
DDC_B15_VRP: R167.1 U11.C22(IO_L12N_VRP_15)
DDC_B16_VRN: R162.2 U11.A4(IO_L12P_VRN_16)
DDC_B16_VRP: R161.1 U11.A5(IO_L12N_VRP_16)
DDC_DCLK_A_DPN: R186.2 U5.AJ29(IO_L9N_CC_21) U11.B21(IO_L11N_CC_15)
DDC_DCLK_A_DPP: R186.1 U5.AK29(IO_L9P_CC_21) U11.C21(IO_L11P_CC_15)
DDC_DCLK_B_DPN: R177.2 U5.AH8(IO_L9N_CC_22) U11.A7(IO_L9N_CC_16)
DDC_DCLK_B_DPP: R177.1 U5.AG8(IO_L9P_CC_22) U11.B7(IO_L9P_CC_16)
DDC_DCLK_C_DPN: R231.2 U5.AA31(IO_L9N_CC_17) U11.K20(IO_L9N_CC_11)
DDC_DCLK_C_DPP: R231.1 U5.AB31(IO_L9P_CC_17) U11.K21(IO_L9P_CC_11)
DDC_DCLK_D_DPN: R234.2 U5.W4(IO_L9N_CC_18) U11.L5(IO_L10N_CC_12)
DDC_DCLK_D_DPP: R234.1 U5.Y4(IO_L9P_CC_18) U11.K5(IO_L10P_CC_12)
DDC_DIN_A0_DPN: R173.2 U5.AA26(IO_L0N_21) U11.A15(IO_L1N_15)
DDC_DIN_A0_DPP: R173.1 U5.AA25(IO_L0P_21) U11.A14(IO_L1P_15)
DDC_DIN_A1_DPN: R189.2 U5.AC27(IO_L1N_21) U11.B14(IO_L0N_15)
DDC_DIN_A1_DPP: R189.1 U5.AB27(IO_L1P_21) U11.C14(IO_L0P_15)
DDC_DIN_A2_DPN: R182.2 U5.AA24(IO_L2N_21) U11.B16(IO_L2N_15)
DDC_DIN_A2_DPP: R182.1 U5.Y24(IO_L2P_21) U11.B15(IO_L2P_15)
DDC_DIN_A3_DPN: R198.2 U5.AB26(IO_L3N_21) U11.C16(IO_L3N_15)
DDC_DIN_A3_DPP: R198.1 U5.AB25(IO_L3P_21) U11.D16(IO_L3P_15)
DDC_DIN_A4_DPN: R176.2 U5.AD27(IO_L4N_VREF_21) U11.A17(IO_L5N_15)
DDC_DIN_A4_DPP: R176.1 U5.AC28(IO_L4P_21) U11.B17(IO_L5P_15)
DDC_DIN_A5_DPN: R164.2 U5.AA28(IO_L5N_21) U11.C17(IO_L4N_VREF_15)
DDC_DIN_A5_DPP: R164.1 U5.AB28(IO_L5P_21) U11.D18(IO_L4P_15)
DDC_DIN_A6_DPN: R170.2 U5.AH28(IO_L6N_21) U11.A19(IO_L6N_15)
DDC_DIN_A6_DPP: R170.1 U5.AG28(IO_L6P_21) U11.A18(IO_L6P_15)
DDC_DIN_A7_DPN: R163.2 U5.AF28(IO_L7N_21) U11.C18(IO_L7N_15)
DDC_DIN_A7_DPP: R163.1 U5.AE28(IO_L7P_21) U11.B19(IO_L7P_15)
DDC_DIN_A8_DPN: R195.2 U5.AK27(IO_L10N_CC_21) U11.D19(IO_L9N_CC_15)
DDC_DIN_A8_DPP: R195.1 U5.AK28(IO_L10P_CC_21) U11.C19(IO_L9P_CC_15)
DDC_DIN_A9_DPN: R178.2 U5.AJ26(IO_L11N_CC_21) U11.B20(IO_L8N_CC_15)
DDC_DIN_A9_DPP: R178.1 U5.AH27(IO_L11P_CC_21) U11.A20(IO_L8P_CC_15)
DDC_DIN_A10_DPN: R180.2 U5.AH25(IO_L12N_VRP_21) U11.A22(IO_L13N_15)
DDC_DIN_A10_DPP: R180.1 U5.AJ25(IO_L12P_VRN_21) U11.B22(IO_L13P_15)
DDC_DIN_A11_DPN: R175.2 U5.AG25(IO_L13N_21) U11.A24(IO_L14N_VREF_15)
DDC_DIN_A11_DPP: R175.1 U5.AF24(IO_L13P_21) U11.A23(IO_L14P_15)
DDC_DIN_A12_DPN: R166.2 U5.AG26(IO_L14N_VREF_21) U11.C23(IO_L15N_15)
DDC_DIN_A12_DPP: R166.1 U5.AG27(IO_L14P_21) U11.B24(IO_L15P_15)
DDC_DIN_A13_DPN: R194.2 U5.AF26(IO_L15N_21) U11.C24(IO_L16N_15)
DDC_DIN_A13_DPP: R194.1 U5.AF25(IO_L15P_21) U11.D24(IO_L16P_15)
DDC_DIN_A14_DPN: R179.2 U5.AE26(IO_L16N_21) U11.A25(IO_L17N_15)
DDC_DIN_A14_DPP: R179.1 U5.AE27(IO_L16P_21) U11.B25(IO_L17P_15)
DDC_DIN_A15_DPN: R188.2 U5.AC24(IO_L17N_21) U11.C26(IO_L18N_15)
DDC_DIN_A15_DPP: R188.1 U5.AC25(IO_L17P_21) U11.B26(IO_L18P_15)
DDC_DIN_B0_DPN: R171.2 U5.AA11(IO_L0N_22) U11.A12(IO_L3N_16)
DDC_DIN_B0_DPP: R171.1 U5.AA10(IO_L0P_22) U11.A13(IO_L3P_16)
DDC_DIN_B1_DPN: R190.2 U5.AA9(IO_L1N_22) U11.B12(IO_L2N_16)
DDC_DIN_B1_DPP: R190.1 U5.AA8(IO_L1P_22) U11.C13(IO_L2P_16)
DDC_DIN_B2_DPN: R201.2 U5.AB10(IO_L2N_22) U11.D10(IO_L0N_16)
DDC_DIN_B2_DPP: R201.1 U5.AB11(IO_L2P_22) U11.D11(IO_L0P_16)
DDC_DIN_B3_DPN: R191.2 U5.AB7(IO_L3N_22) U11.C12(IO_L1N_16)
DDC_DIN_B3_DPP: R191.1 U5.AB8(IO_L3P_22) U11.C11(IO_L1P_16)
DDC_DIN_B4_DPN: R165.2 U5.AC7(IO_L4N_VREF_22) U11.A10(IO_L6N_16)
DDC_DIN_B4_DPP: R165.1 U5.AC8(IO_L4P_22) U11.B11(IO_L6P_16)
DDC_DIN_B5_DPN: R196.2 U5.AJ6(IO_L5N_22) U11.D9(IO_L4N_VREF_16)
DDC_DIN_B5_DPP: R196.1 U5.AJ7(IO_L5P_22) U11.C9(IO_L4P_16)
DDC_DIN_B6_DPN: R183.2 U5.AD7(IO_L6N_22) U11.B10(IO_L5N_16)
DDC_DIN_B6_DPP: R183.1 U5.AE7(IO_L6P_22) U11.B9(IO_L5P_16)
DDC_DIN_B7_DPN: R172.2 U5.AH7(IO_L7N_22) U11.A8(IO_L7N_16)
DDC_DIN_B7_DPP: R172.1 U5.AG7(IO_L7P_22) U11.A9(IO_L7P_16)
DDC_DIN_B8_DPN: R202.2 U5.AF8(IO_L10N_CC_22) U11.D6(IO_L10N_CC_16)
DDC_DIN_B8_DPP: R202.1 U5.AE8(IO_L10P_CC_22) U11.D5(IO_L10P_CC_16)
DDC_DIN_B9_DPN: R192.2 U5.AD10(IO_L11N_CC_22) U11.C7(IO_L11N_CC_16)
DDC_DIN_B9_DPP: R192.1 U5.AC10(IO_L11P_CC_22) U11.C6(IO_L11P_CC_16)
DDC_DIN_B10_DPN: R181.2 U5.AK7(IO_L12N_VRP_22) U11.B6(IO_L13N_16)
DDC_DIN_B10_DPP: R181.1 U5.AK6(IO_L12P_VRN_22) U11.B5(IO_L13P_16)
DDC_DIN_B11_DPN: R203.2 U5.AF9(IO_L13N_22) U11.D4(IO_L14N_VREF_16)
DDC_DIN_B11_DPP: R203.1 U5.AE9(IO_L13P_22) U11.D3(IO_L14P_16)
DDC_DIN_B12_DPN: R187.2 U5.AJ9(IO_L14N_VREF_22) U11.B4(IO_L15N_16)
DDC_DIN_B12_DPP: R187.1 U5.AH9(IO_L14P_22) U11.C4(IO_L15P_16)
DDC_DIN_B13_DPN: R193.2 U5.AG10(IO_L15N_22) U11.C3(IO_L16N_16)
DDC_DIN_B13_DPP: R193.1 U5.AF10(IO_L15P_22) U11.C2(IO_L16P_16)
DDC_DIN_B14_DPN: R174.2 U5.AK8(IO_L16N_22) U11.A3(IO_L17N_16)
DDC_DIN_B14_DPP: R174.1 U5.AK9(IO_L16P_22) U11.A2(IO_L17P_16)
DDC_DIN_B15_DPN: R184.2 U5.AF11(IO_L17N_22) U11.B2(IO_L19N_16)
DDC_DIN_B15_DPP: R184.1 U5.AG11(IO_L17P_22) U11.B1(IO_L19P_16)
DDC_DIN_C0_DPN: R206.2 U5.V24(IO_L0N_17) U11.E20(IO_L1N_11)
DDC_DIN_C0_DPP: R206.1 U5.W24(IO_L0P_17) U11.E21(IO_L1P_11)
DDC_DIN_C1_DPN: R212.2 U5.W26(IO_L1N_17) U11.F20(IO_L0N_11)
DDC_DIN_C1_DPP: R212.1 U5.Y26(IO_L1P_17) U11.G20(IO_L0P_11)
DDC_DIN_C2_DPN: R224.2 U5.W25(IO_L2N_17) U11.H19(IO_L6N_11)
DDC_DIN_C2_DPP: R224.1 U5.V25(IO_L2P_17) U11.J19(IO_L6P_11)
DDC_DIN_C3_DPN: R205.2 U5.W27(IO_L3N_17) U11.E23(IO_L2N_11)
DDC_DIN_C3_DPP: R205.1 U5.Y27(IO_L3P_17) U11.E22(IO_L2P_11)
DDC_DIN_C4_DPN: R209.2 U5.W30(IO_L4N_VREF_17) U11.F23(IO_L3N_11)
DDC_DIN_C4_DPP: R209.1 U5.V30(IO_L4P_17) U11.F22(IO_L3P_11)
DDC_DIN_C5_DPN: R215.2 U5.V27(IO_L5N_17) U11.G22(IO_L4N_VREF_11)
DDC_DIN_C5_DPP: R215.1 U5.V28(IO_L5P_17) U11.G21(IO_L4P_11)
DDC_DIN_C6_DPN: R229.2 U5.Y31(IO_L6N_17) U11.J20(IO_L8N_CC_11)
DDC_DIN_C6_DPP: R229.1 U5.W31(IO_L6P_17) U11.J21(IO_L8P_CC_11)
DDC_DIN_C7_DPN: R221.2 U5.V29(IO_L7N_17) U11.H22(IO_L5N_11)
DDC_DIN_C7_DPP: R221.1 U5.W29(IO_L7P_17) U11.H21(IO_L5P_11)
DDC_DIN_C8_DPN: R223.2 U5.AB30(IO_L10N_CC_17) U11.J23(IO_L7N_11)
DDC_DIN_C8_DPP: R223.1 U5.AC30(IO_L10P_CC_17) U11.H23(IO_L7P_11)
DDC_DIN_C9_DPN: R230.2 U5.AA30(IO_L11N_CC_17) U11.K22(IO_L10N_CC_11)
DDC_DIN_C9_DPP: R230.1 U5.AA29(IO_L11P_CC_17) U11.K23(IO_L10P_CC_11)
DDC_DIN_C10_DPN: R240.2 U5.AE31(IO_L12N_VRP_17) U11.M19(IO_L15N_11)
DDC_DIN_C10_DPP: R240.1 U5.AD31(IO_L12P_VRN_17) U11.M20(IO_L15P_11)
DDC_DIN_C11_DPN: R239.2 U5.AC29(IO_L13N_17) U11.M21(IO_L13N_11)
DDC_DIN_C11_DPP: R239.1 U5.AD30(IO_L13P_17) U11.M22(IO_L13P_11)
DDC_DIN_C12_DPN: R246.2 U5.AG31(IO_L14N_VREF_17) U11.N19(IO_L14N_VREF_11)
DDC_DIN_C12_DPP: R246.1 U5.AF31(IO_L14P_17) U11.P19(IO_L14P_11)
DDC_DIN_C13_DPN: R242.2 U5.AD29(IO_L15N_17) U11.N21(IO_L17N_11)
DDC_DIN_C13_DPP: R242.1 U5.AE29(IO_L15P_17) U11.N22(IO_L17P_11)
DDC_DIN_C14_DPN: R250.2 U5.AK31(IO_L16N_17) U11.P20(IO_L19N_11)
DDC_DIN_C14_DPP: R250.1 U5.AJ31(IO_L16P_17) U11.P21(IO_L19P_11)
DDC_DIN_C15_DPN: R247.2 U5.AF30(IO_L17N_17) U11.N23(IO_L16N_11)
DDC_DIN_C15_DPP: R247.1 U5.AF29(IO_L17P_17) U11.P23(IO_L16P_11)
DDC_DIN_D0_DPN: R254.2 U5.W11(IO_L0N_18) U11.T3(IO_L17N_12)
DDC_DIN_D0_DPP: R254.1 U5.Y11(IO_L0P_18) U11.R3(IO_L17P_12)
DDC_DIN_D1_DPN: R253.2 U5.Y9(IO_L1N_18) U11.R5(IO_L18N_12)
DDC_DIN_D1_DPP: R253.1 U5.W9(IO_L1P_18) U11.R6(IO_L18P_12)
DDC_DIN_D2_DPN: R252.2 U5.V10(IO_L2N_18) U11.R7(IO_L19N_12)
DDC_DIN_D2_DPP: R252.1 U5.W10(IO_L2P_18) U11.P6(IO_L19P_12)
DDC_DIN_D3_DPN: R245.2 U5.V8(IO_L3N_18) U11.N3(IO_L14N_VREF_12)
DDC_DIN_D3_DPP: R245.1 U5.V9(IO_L3P_18) U11.P3(IO_L14P_12)
DDC_DIN_D4_DPN: R251.2 U5.V7(IO_L4N_VREF_18) U11.P4(IO_L16N_12)
DDC_DIN_D4_DPP: R251.1 U5.W7(IO_L4P_18) U11.P5(IO_L16P_12)
DDC_DIN_D5_DPN: R243.2 U5.V5(IO_L5N_18) U11.N6(IO_L13N_12)
DDC_DIN_D5_DPP: R243.1 U5.W5(IO_L5P_18) U11.N7(IO_L13P_12)
DDC_DIN_D6_DPN: R241.2 U5.Y8(IO_L6N_18) U11.N4(IO_L15N_12)
DDC_DIN_D6_DPP: R241.1 U5.Y7(IO_L6P_18) U11.M4(IO_L15P_12)
DDC_DIN_D7_DPN: R238.2 U5.W6(IO_L7N_18) U11.M7(IO_L9N_CC_12)
DDC_DIN_D7_DPP: R238.1 U5.Y6(IO_L7P_18) U11.L7(IO_L9P_CC_12)
DDC_DIN_D8_DPN: R232.2 U5.AB5(IO_L10N_CC_18) U11.K7(IO_L8N_CC_12)
DDC_DIN_D8_DPP: R232.1 U5.AA4(IO_L10P_CC_18) U11.K6(IO_L8P_CC_12)
DDC_DIN_D9_DPN: R226.2 U5.AC5(IO_L11N_CC_18) U11.J4(IO_L7N_12)
DDC_DIN_D9_DPP: R226.1 U5.AB6(IO_L11P_CC_18) U11.J5(IO_L7P_12)
DDC_DIN_D10_DPN: R225.2 U5.AD4(IO_L12N_VRP_18) U11.H7(IO_L4N_VREF_12)
DDC_DIN_D10_DPP: R225.1 U5.AC4(IO_L12P_VRN_18) U11.J6(IO_L4P_12)
DDC_DIN_D11_DPN: R218.2 U5.AD6(IO_L13N_18) U11.G4(IO_L6N_12)
DDC_DIN_D11_DPP: R218.1 U5.AD5(IO_L13P_18) U11.H4(IO_L6P_12)
DDC_DIN_D12_DPN: R220.2 U5.AF4(IO_L14N_VREF_18) U11.G5(IO_L5N_12)
DDC_DIN_D12_DPP: R220.1 U5.AE4(IO_L14P_18) U11.H6(IO_L5P_12)
DDC_DIN_D13_DPN: R216.2 U5.AE6(IO_L15N_18) U11.G7(IO_L2N_12)
DDC_DIN_D13_DPP: R216.1 U5.AF5(IO_L15P_18) U11.G6(IO_L2P_12)
DDC_DIN_D14_DPN: R210.2 U5.AJ4(IO_L16N_18) U11.F4(IO_L3N_12)
DDC_DIN_D14_DPP: R210.1 U5.AH4(IO_L16P_18) U11.F5(IO_L3P_12)
DDC_DIN_D15_DPN: R207.2 U5.AG6(IO_L17N_18) U11.E5(IO_L1N_12)
DDC_DIN_D15_DPP: R207.1 U5.AF6(IO_L17P_18) U11.E6(IO_L1P_12)
DDC_VERSION_0: U5.AH20(IO_L2N_GC_D10_4) ; also on sheet 11
DDC_VERSION_1: U5.AG13(IO_L1P_GC_D13_4) ; also on sheet 11
DDC_VERSION_2: U5.AF18(IO_L9N_CC_GC_4) ; also on sheet 11
DDR2_A0: J15.102(A0) RP7.4 ; also on sheet 6
DDR2_A1: J15.101(A1) RP9.2 ; also on sheet 6
DDR2_A2: J15.100(A2) RP7.3 ; also on sheet 6
DDR2_A3: J15.99(A3) RP8.3 ; also on sheet 6
DDR2_A4: J15.98(A4) RP7.2 ; also on sheet 6
DDR2_A5: J15.97(A5) RP8.1 ; also on sheet 6
DDR2_A6: J15.94(A6) RP7.1 ; also on sheet 6
DDR2_A7: J15.92(A7) RP6.4 ; also on sheet 6
DDR2_A8: J15.93(A8) RP5.4 ; also on sheet 6
DDR2_A9: J15.91(A9) RP5.3 ; also on sheet 6
DDR2_A10: J15.105(A10/AP) RP9.3 ; also on sheet 6
DDR2_A11: J15.90(A11) RP6.3 ; also on sheet 6
DDR2_A12: J15.89(A12) RP5.2 ; also on sheet 6
DDR2_A13: J15.116(A13) RP9.4 ; also on sheet 6
DDR2_A14: J15.86(NC7) RP6.1 ; also on sheet 6
DDR2_A15: J15.84(NC6) RP6.2 ; also on sheet 6
DDR2_BA0: J15.107(BA0) RP10.2 ; also on sheet 6
DDR2_BA1: J15.106(BA1) RP8.2 ; also on sheet 6
DDR2_BA2: J15.85(BA2) RP5.1 ; also on sheet 6
DDR2_CAS_B: J15.113(~{CAS}) RP10.3 ; also on sheet 6
DDR2_CK0_N: C177.2 J15.32(CK0_N) ; also on sheet 6
DDR2_CK0_P: C177.1 J15.30(CK0_P) ; also on sheet 6
DDR2_CK1_N: C264.2 J15.166(CK1_N) ; also on sheet 6
DDR2_CK1_P: C264.1 J15.164(CK1_P) ; also on sheet 6
DDR2_CKE0: J15.79(CKE0) R154.1 ; also on sheet 6
DDR2_CKE1: J15.80(CKE1) R157.1 ; also on sheet 6
DDR2_CS0_B: J15.110(~{S0}) RP9.1 ; also on sheet 6
DDR2_CS1_B: J15.115(~{S1}) RP10.4 ; also on sheet 6
DDR2_D0: J15.5(DQ0) ; also on sheet 6
DDR2_D1: J15.7(DQ1) ; also on sheet 6
DDR2_D2: J15.17(DQ2) ; also on sheet 6
DDR2_D3: J15.19(DQ3) ; also on sheet 6
DDR2_D4: J15.4(DQ4) ; also on sheet 6
DDR2_D5: J15.6(DQ5) ; also on sheet 6
DDR2_D6: J15.14(DQ6) ; also on sheet 6
DDR2_D7: J15.16(DQ7) ; also on sheet 6
DDR2_D8: J15.23(DQ8) ; also on sheet 6
DDR2_D9: J15.25(DQ9) ; also on sheet 6
DDR2_D10: J15.35(DQ10) ; also on sheet 6
DDR2_D11: J15.37(DQ11) ; also on sheet 6
DDR2_D12: J15.20(DQ12) ; also on sheet 6
DDR2_D13: J15.22(DQ13) ; also on sheet 6
DDR2_D14: J15.36(DQ14) ; also on sheet 6
DDR2_D15: J15.38(DQ15) ; also on sheet 6
DDR2_D16: J15.43(DQ16) ; also on sheet 6
DDR2_D17: J15.45(DQ17) ; also on sheet 6
DDR2_D18: J15.55(DQ18) ; also on sheet 6
DDR2_D19: J15.57(DQ19) ; also on sheet 6
DDR2_D20: J15.44(DQ20) ; also on sheet 6
DDR2_D21: J15.46(DQ21) ; also on sheet 6
DDR2_D22: J15.56(DQ22) ; also on sheet 6
DDR2_D23: J15.58(DQ23) ; also on sheet 6
DDR2_D24: J15.61(DQ24) ; also on sheet 6
DDR2_D25: J15.63(DQ25) ; also on sheet 6
DDR2_D26: J15.73(DQ26) ; also on sheet 6
DDR2_D27: J15.75(DQ27) ; also on sheet 6
DDR2_D28: J15.62(DQ28) ; also on sheet 6
DDR2_D29: J15.64(DQ29) ; also on sheet 6
DDR2_D30: J15.74(DQ30) ; also on sheet 6
DDR2_D31: J15.76(DQ31) ; also on sheet 6
DDR2_D32: J15.123(DQ32) ; also on sheet 6
DDR2_D33: J15.125(DQ33) ; also on sheet 6
DDR2_D34: J15.135(DQ34) ; also on sheet 6
DDR2_D35: J15.137(DQ35) ; also on sheet 6
DDR2_D36: J15.124(DQ36) ; also on sheet 6
DDR2_D37: J15.126(DQ37) ; also on sheet 6
DDR2_D38: J15.134(DQ38) ; also on sheet 6
DDR2_D39: J15.136(DQ39) ; also on sheet 6
DDR2_D40: J15.141(DQ40) ; also on sheet 6
DDR2_D41: J15.143(DQ41) ; also on sheet 6
DDR2_D42: J15.151(DQ42) ; also on sheet 6
DDR2_D43: J15.153(DQ43) ; also on sheet 6
DDR2_D44: J15.140(DQ44) ; also on sheet 6
DDR2_D45: J15.142(DQ45) ; also on sheet 6
DDR2_D46: J15.152(DQ46) ; also on sheet 6
DDR2_D47: J15.154(DQ47) ; also on sheet 6
DDR2_D48: J15.157(DQ48) ; also on sheet 6
DDR2_D49: J15.159(DQ49) ; also on sheet 6
DDR2_D50: J15.173(DQ50) ; also on sheet 6
DDR2_D51: J15.175(DQ51) ; also on sheet 6
DDR2_D52: J15.158(DQ52) ; also on sheet 6
DDR2_D53: J15.160(DQ53) ; also on sheet 6
DDR2_D54: J15.174(DQ54) ; also on sheet 6
DDR2_D55: J15.176(DQ55) ; also on sheet 6
DDR2_D56: J15.179(DQ56) ; also on sheet 6
DDR2_D57: J15.181(DQ57) ; also on sheet 6
DDR2_D58: J15.189(DQ58) ; also on sheet 6
DDR2_D59: J15.191(DQ59) ; also on sheet 6
DDR2_D60: J15.180(DQ60) ; also on sheet 6
DDR2_D61: J15.182(DQ61) ; also on sheet 6
DDR2_D62: J15.192(DQ62) ; also on sheet 6
DDR2_D63: J15.194(DQ63) ; also on sheet 6
DDR2_DM0: J15.10(DM0) ; also on sheet 6
DDR2_DM1: J15.26(DM1) ; also on sheet 6
DDR2_DM2: J15.52(DM2) ; also on sheet 6
DDR2_DM3: J15.67(DM3) ; also on sheet 6
DDR2_DM4: J15.130(DM4) ; also on sheet 6
DDR2_DM5: J15.147(DM5) ; also on sheet 6
DDR2_DM6: J15.170(DM6) ; also on sheet 6
DDR2_DM7: J15.185(DM7) ; also on sheet 6
DDR2_DQS0_N: J15.11(DQS0_N) ; also on sheet 6
DDR2_DQS0_P: J15.13(DQS0_P) ; also on sheet 6
DDR2_DQS1_N: J15.29(DQS1_N) ; also on sheet 6
DDR2_DQS1_P: J15.31(DQS1_P) ; also on sheet 6
DDR2_DQS2_N: J15.49(DQS2_N) ; also on sheet 6
DDR2_DQS2_P: J15.51(DQS2_P) ; also on sheet 6
DDR2_DQS3_N: J15.68(DQS3_N) ; also on sheet 6
DDR2_DQS3_P: J15.70(DQS3_P) ; also on sheet 6
DDR2_DQS4_N: J15.129(DQS4_N) ; also on sheet 6
DDR2_DQS4_P: J15.131(DQS4_P) ; also on sheet 6
DDR2_DQS5_N: J15.146(DQS5_N) ; also on sheet 6
DDR2_DQS5_P: J15.148(DQS5_P) ; also on sheet 6
DDR2_DQS6_N: J15.167(DQS6_N) ; also on sheet 6
DDR2_DQS6_P: J15.169(DQS6_P) ; also on sheet 6
DDR2_DQS7_N: J15.186(DQS7_N) ; also on sheet 6
DDR2_DQS7_P: J15.188(DQS7_P) ; also on sheet 6
DDR2_ODT0: J15.114(ODT0) R52.1 ; also on sheet 6
DDR2_ODT1: J15.119(ODT1) R204.1 ; also on sheet 6
DDR2_RAS_B: J15.108(~{RAS}) RP8.4 ; also on sheet 6
DDR2_SA0: J15.198(SA0) R259.1
DDR2_SA1: J15.200(SA1) R257.2
DDR2_SCL: J15.197(SCL) ; also on sheet 5 22
DDR2_SDA: J15.195(SDA) ; also on sheet 5 22
DDR2_WE_B: J15.109(~{WE}) RP10.1 ; also on sheet 6
DIP_SW0: U5.G20(IO_L5P_GC_3) ; also on sheet 4
DIP_SW1: U5.G21(IO_L7P_GC_3) ; also on sheet 4
DIP_SW2: U5.F20(IO_L5N_GC_3) ; also on sheet 4
DIP_SW3: U5.G22(IO_L7N_GC_3) ; also on sheet 4
DIP_SW4: U5.H15(IO_L4N_GC_VREF_3) ; also on sheet 4
DIP_SW5: U5.H14(IO_L6N_GC_3) ; also on sheet 4
DIP_SW6: U5.H13(IO_L6P_GC_3) ; also on sheet 4
DIP_SW7: U5.J14(IO_L4P_GC_3) ; also on sheet 4
DVALID_A_DPN: R200.2 U5.AJ27(IO_L8N_CC_21) U11.D20(IO_L10N_CC_15)
DVALID_A_DPP: R200.1 U5.AK26(IO_L8P_CC_21) U11.D21(IO_L10P_CC_15)
DVALID_B_DPN: R197.2 U5.AC9(IO_L8N_CC_22) U11.C8(IO_L8N_CC_16)
DVALID_B_DPP: R197.1 U5.AD9(IO_L8P_CC_22) U11.D8(IO_L8P_CC_16)
DVALID_C_DPN: R236.2 U5.Y29(IO_L8N_CC_17) U11.L19(IO_L11N_CC_11)
DVALID_C_DPP: R236.1 U5.Y28(IO_L8P_CC_17) U11.L20(IO_L11P_CC_11)
DVALID_D_DPN: R237.2 U5.AA5(IO_L8N_CC_18) U11.L3(IO_L11N_CC_12)
DVALID_D_DPP: R237.1 U5.AA6(IO_L8P_CC_18) U11.L4(IO_L11P_CC_12)
EXP1_DIFF_CLK_IN_DPN: U5.H20(IO_L1N_CC_GC_3) ; also on sheet 17
EXP1_DIFF_CLK_IN_DPP: U5.H19(IO_L1P_CC_GC_3) ; also on sheet 17
EXP1_SE_CLK_IN: U5.J20(IO_L3P_GC_3) ; also on sheet 17
EXP1_SE_CLK_OUT: U5.J21(IO_L3N_GC_3) ; also on sheet 17
EXP2_DIFF_CLK_IN_DPN: U5.J17(IO_L0N_CC_GC_3) ; also on sheet 18
EXP2_DIFF_CLK_IN_DPP: U5.H18(IO_L0P_CC_GC_3) ; also on sheet 18
EXP2_SE_CLK_IN: U5.J16(IO_L2P_GC_VRN_3) ; also on sheet 18
EXP2_SE_CLK_OUT: U5.J15(IO_L2N_GC_VRP_3) ; also on sheet 18
FINISHED: D16.1(ANODE) ; also on sheet 5
FLASH_CS#: R6.2 U3.11(~{CS}) ; also on sheet 5
FLASH_RDY: R16.2 U3.1(RDY/~{BUSY}) U6.3(A2)
FLASH_RST#: R9.2 U3.2(~{RESET})
FLASH_SCK: U2.2(A1) U3.12(SCK/CLK)
FLASH_SER: R36.2 U3.16(SER/~{BYTE})
FLASH_SI: U2.3(A2) U3.13(SI)
FLASH_SO: R5.2 U3.14(SO) U6.2(A1)
FLASH_WP#: R7.2 U3.3(~{WP})
GPIO_A0: U5.AG20(IO_L6N_GC_4) ; also on sheet 4
GPIO_A1: U5.AF20(IO_L8P_CC_GC_4) ; also on sheet 4
GPIO_A2: U5.AF19(IO_L8N_CC_GC_4) ; also on sheet 4
GPIO_A3: U5.AH19(IO_L6P_GC_4) ; also on sheet 4
GPIO_A4: U5.AG17(IO_L7P_GC_VRN_4) ; also on sheet 4
GPIO_A5: U5.AG16(IO_L7N_GC_VRP_4) ; also on sheet 4
GPIO_A6: U5.AH12(IO_L3P_GC_D9_4) ; also on sheet 4
GPIO_A7: U5.AG12(IO_L3N_GC_D8_4) ; also on sheet 4
INIT_ACTIVE: U5.AF21(IO_L0N_GC_D14_4) ; also on sheet 11
LED0: U5.AK19(IO_L4P_GC_4) ; also on sheet 4
LED1: U5.AJ19(IO_L4N_GC_VREF_4) ; also on sheet 4
NS_FLIP: U5.AE24(IO_L19N_21) ; also on sheet 11
RESET: U5.AG15(IO_L5P_GC_4) ; also on sheet 19
ROWAD_0: U5.AJ10(IO_L18P_22) ; also on sheet 11
ROWAD_1: U5.AH10(IO_L18N_22) ; also on sheet 11
ROWAD_2: U5.AD11(IO_L19P_22) ; also on sheet 11
ROWAD_3: U5.AE11(IO_L19N_22) ; also on sheet 11
ROWAD_4: U5.AJ30(IO_L18P_17) ; also on sheet 11
ROWAD_5: U5.AH30(IO_L18N_17) ; also on sheet 11
ROWAD_6: U5.AH29(IO_L19P_17) ; also on sheet 11
ROWAD_7: U5.AG30(IO_L19N_17) ; also on sheet 11
ROWAD_8: U5.AD26(IO_L18P_21) ; also on sheet 11
ROWAD_9: U5.AD25(IO_L18N_21) ; also on sheet 11
ROWAD_10: U5.AD24(IO_L19P_21) ; also on sheet 11
RST_ACTIVE: U5.AF13(IO_L1N_GC_D12_4) ; also on sheet 11
TCK_JTAG: H1.6 U5.AA13(TCK_0) U10.H3(TCK) ; also on sheet 12
TDI_DDC: R38.2 ; also on sheet 12
TDI_JTAG: H1.10 R737.2 U10.G1(TDI)
TDO_DDC: R40.1 ; also on sheet 12
TDO_JTAG: H1.8 R39.2 R40.2
TDO_V5: R38.1 R39.1 U5.AC14(TDO_0)
TDO_XCF16: R737.1 U5.AC13(TDI_0) U10.E6(TDO)
TMS_JTAG: H1.4 U5.AB13(TMS_0) U10.E2(TMS) ; also on sheet 12
USB_CFG_SEL: R156.2 U21.2(S1) ; also on sheet 22
USB_FPGA_CLK: U21.5(1B2) U21.6(1B1) ; also on sheet 22
USB_FPGA_D: U21.10(2B1) U21.11(2B2) ; also on sheet 22
USB_FPGA_DONE_IV: R2.2 ; also on sheet 22
USB_FPGA_INIT_B: R8.2 ; also on sheet 22
USB_FPGA_PROGB: R126.2 ; also on sheet 22
XCF_CCLK: R148.1 R153.1 ; also on sheet 6
XCF_D0: U10.H6(D0) ; also on sheet 6
XCF_DONE: R735.2 U10.B4(~{CE})
XCF_INIT_B: R734.2 U10.A3(OE/~{RESET})
XCF_V5_CCLK: U21.3(1B4) U21.4(1B3) ; also on sheet 6
XCF_V5_D0: U21.12(2B3) U21.13(2B4) ; also on sheet 6
N21444422: D15.2 R263.1
N21444465: BT5.2(-) R261.1
N21444479: BT5.1(+) D15.1
N21570486: D2.1(ANODE) R145.1
N21572782: D16.2(CATHODE) R146.1
N21577554: R153.2 U10.C2(CLKOUT)
N21577700: R148.2 U10.B3(CLK)
N21841068: J4.2 R142.1 U10.G3(REV_SEL0)
N21854268: R57.1 U10.G4(REV_SEL1)
N32058041: C67.1 FB2.2 R45.1 U9.4(VDO)
N32058049: R45.2 U9.1(EN)
N32058067: R44.1 U9.3(OUT)

Not connected (* = marked no-connect by the designer): H1 12* 14*; J15 50(NC4)* 69(NC1)* 83(NC2)* 120(NC5)* 163(NC3)*; U3 4(NC_1)* 5(NC_2)* 8(NC_3)* 9(NC_4)* 10(NC_5)* 15(NC_6)* 17(I/O0)* 18(I/O1)* 19(I/O2)* 20(I/O3)* 23(I/O4)* 24(I/O5)* 25(I/O6)* 26(I/O7)* 27(NC_7)* 28(NC_8)*; U5 AB23(RSVD7)* AC23(RSVD8)* AD14(D_OUT_BUSY_0)*; U10 A4(DNC1)* A5(D6)* A6(D7)* B5(D5)* C1(BUSY)* C3(DNC2)* C4(DNC3)* C5(D4)* D2(~{CEO})* D3(DNC10)* D4(DNC11)* D5(D3)* E3(DNC4)* E4(DNC5)* E5(D2)* F2(DNC6)* F3(DNC7)* F4(DNC8)* G2(DNC9)* H5(D1)*

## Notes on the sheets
sheet 7
- 2.5V
- 2.5V
- 2.5V
- 2.5V
- BANK3 = 2.5V/3.3V
  BANK4 = 2.5V
- NOTE: Do Not Install
- NOTE: Do Not Install
- NOTE: AT45DB642D is obsolete. If
  customers want flash functionality,
  the customer must identify and
  implement a different flash solution.
- DIR     OPERATION
     L            B->A
     H           A->B
- APPS FPGA - 3
- DIR     OPERATION
     L            B->A
     H           A->B
- DLP010
sheet 8
- NOTE: Do Not Install
- 0-1 REVISION SELECT = 00
  1-2 REVISION SELECT = 01
- NOTE: Refer to
  table on Page 11
  to configure M[2:0]
- NOTE: Do Not Install
- NOTE: Do Not Install
- S1        FUNCTION
- 0              A=B1
  1              A=B3
- Red
- Green
- NOTE: Do Not Install
- NOTE: Do Not Install
- APPS FPGA - 4
- DLP010
- NOTE: Do Not Install
sheet 9
- Layout Note: Place near pin 1
- DDR2 SO-DIMM
- DLP010
sheet 10
- 2.5V
- 2.5V
- 2.5V
- 2.5V
- DLPC410 1
- DLP010
